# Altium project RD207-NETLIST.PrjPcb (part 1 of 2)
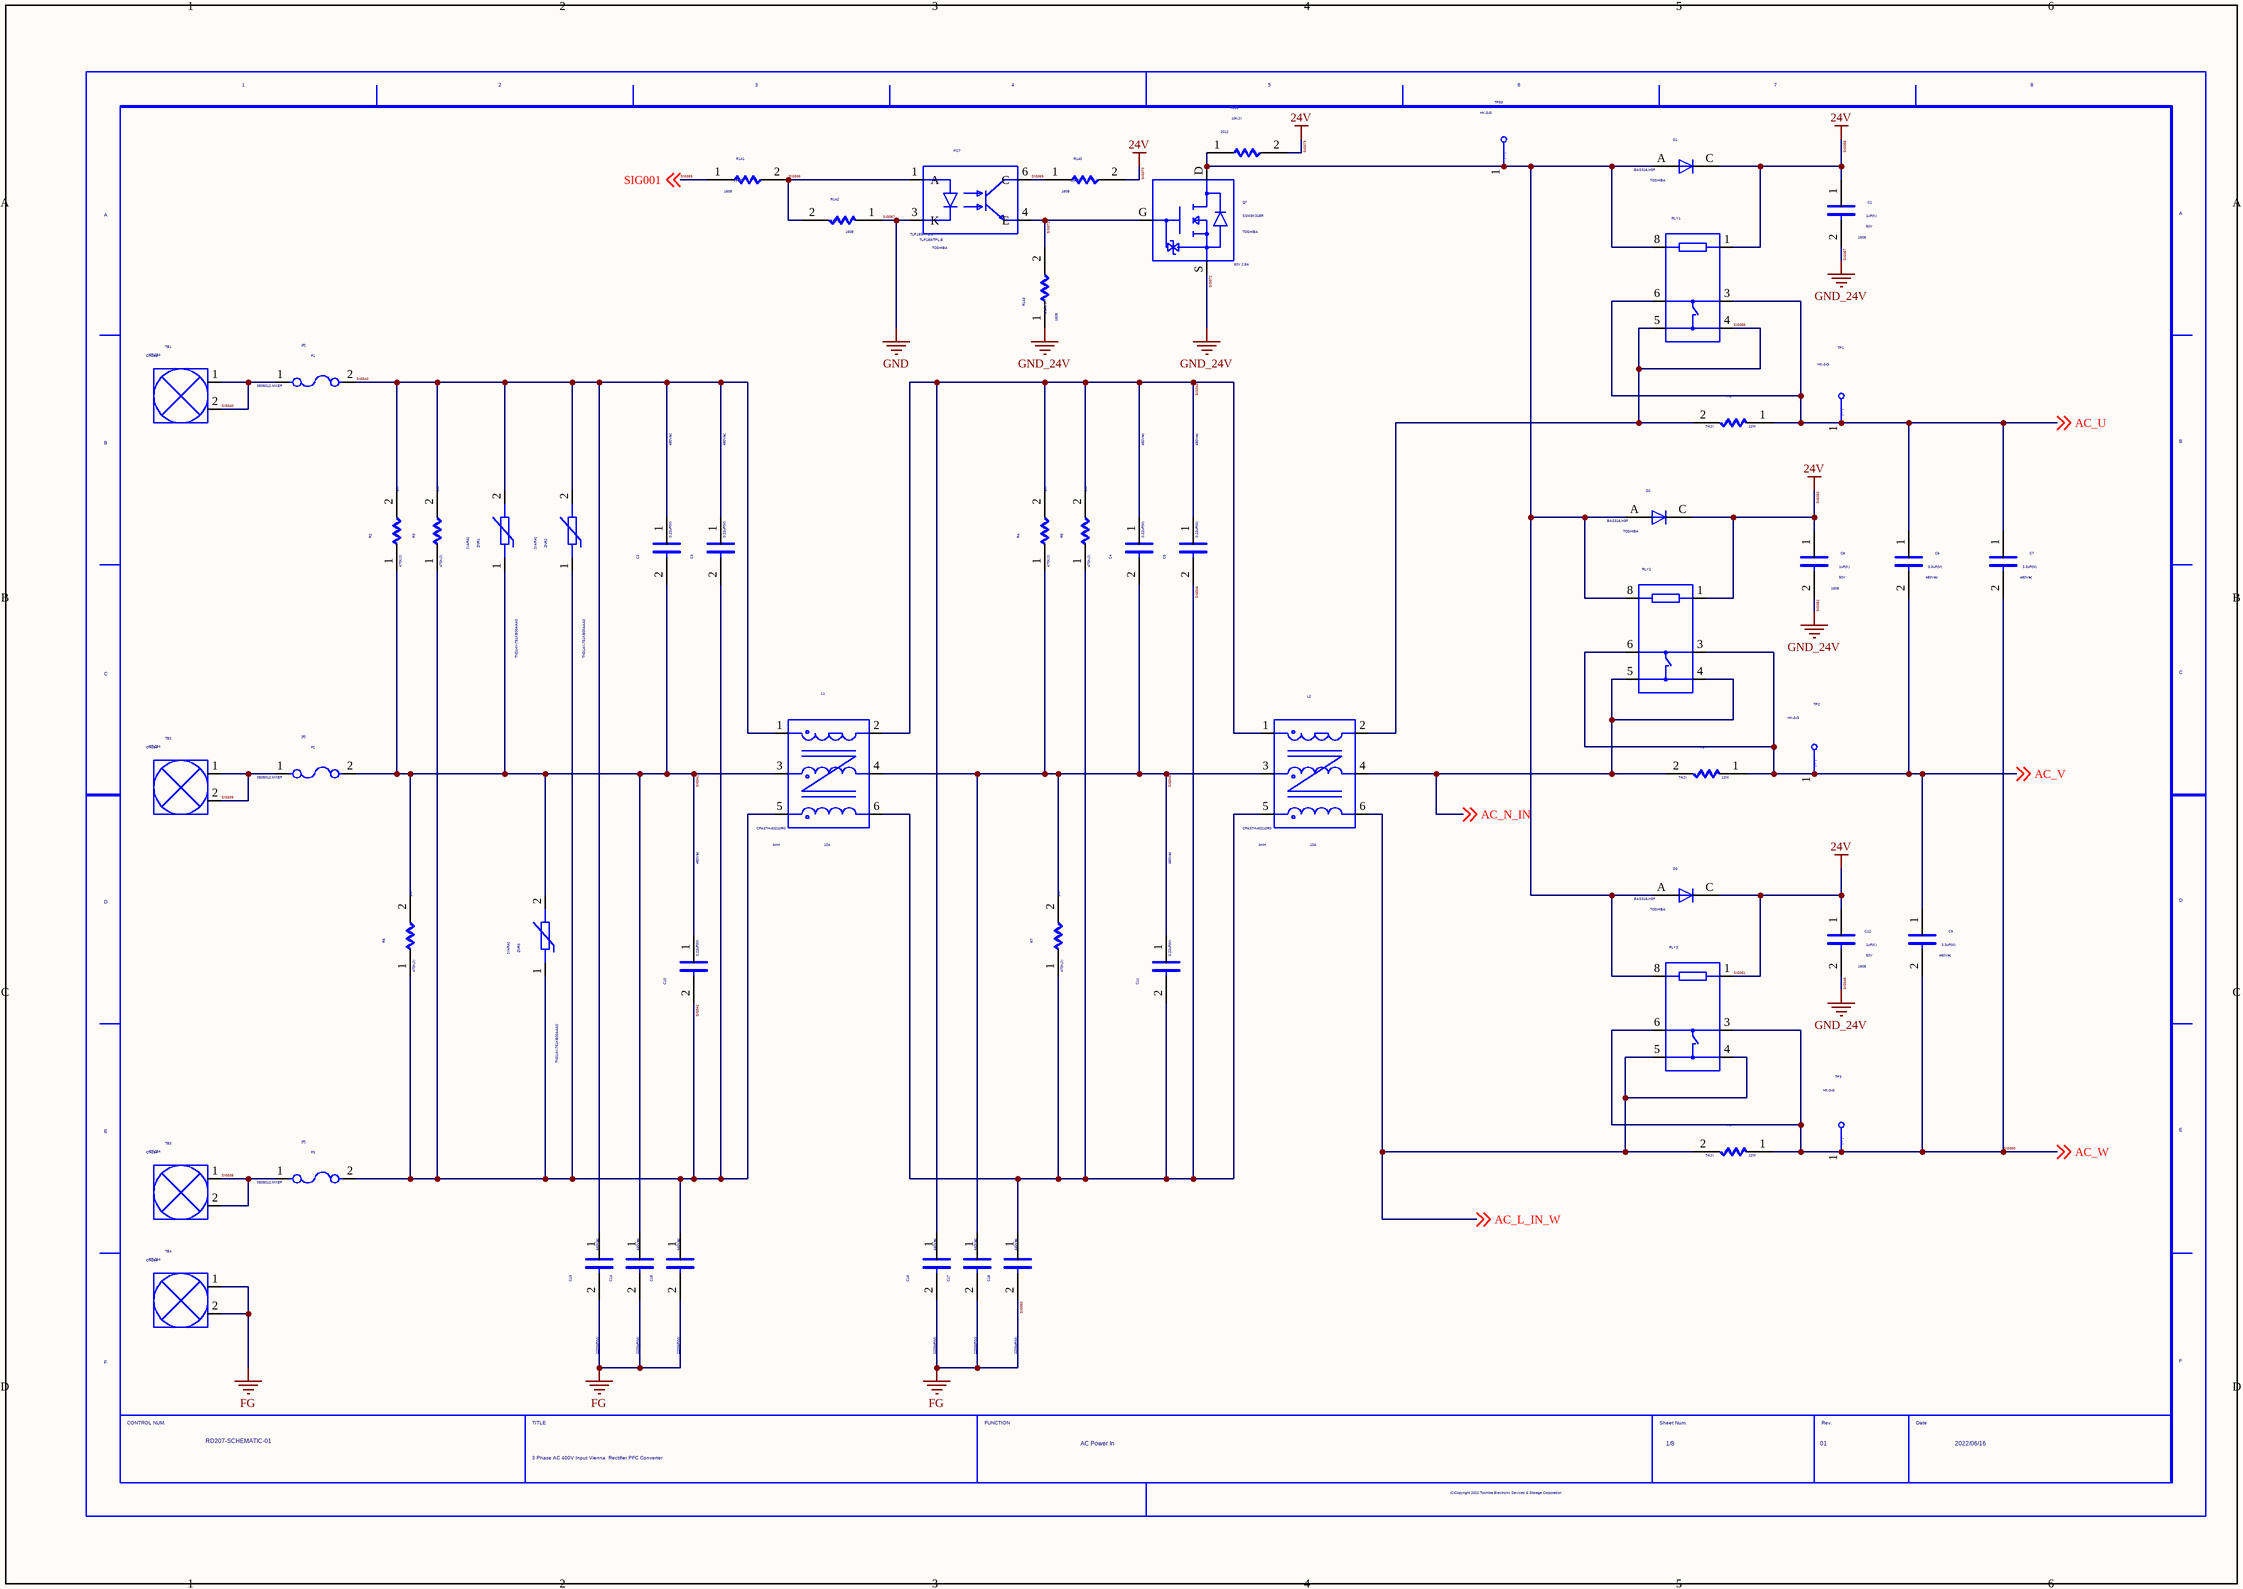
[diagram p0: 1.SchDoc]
8 sheets, 465 parts. Net scope: global (net labels, ports and power ports of the same name join across sheets).
Sheets:
  1.SchDoc
  2.SchDoc
  3.SchDoc
  4.SchDoc
  5.SchDoc
  6.SchDoc
  7.SchDoc
  8.SchDoc

## Sheet 1.SchDoc
size 420 x 297 mm

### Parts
(Parts that share a designator on the sheet are numbered #1, #2 ... from top to bottom, then left to right.)
C1  SIZECODESMD: 1608  VAL2: 50V  VAL1: 1uF(K)  (hidden comment: C)
C2  VAL2: 480Vac  VAL1: 0.22uF(M)  (hidden comment: C)
C3  VAL2: 480Vac  VAL1: 0.22uF(M)  (hidden comment: C)
C4  VAL2: 480Vac  VAL1: 0.22uF(M)  (hidden comment: C)
C5  VAL2: 480Vac  VAL1: 0.22uF(M)  (hidden comment: C)
C6  VAL2: 480Vac  VAL1: 3.3uF(M)  (hidden comment: C)
C7  VAL2: 480Vac  VAL1: 3.3uF(M)  (hidden comment: C)
C8  SIZECODESMD: 1608  VAL2: 50V  VAL1: 1uF(K)  (hidden comment: C)
C9  VAL2: 480Vac  VAL1: 3.3uF(M)  (hidden comment: C)
C10  VAL2: 480Vac  VAL1: 0.22uF(M)  (hidden comment: C)
C11  VAL2: 480Vac  VAL1: 0.22uF(M)  (hidden comment: C)
C12  SIZECODESMD: 1608  VAL2: 50V  VAL1: 1uF(K)  (hidden comment: C)
C13  VAL2: 440Vac  VAL1: 2200pF(M)  (hidden comment: C)
C14  VAL2: 440Vac  VAL1: 2200pF(M)  (hidden comment: C)
C15  VAL2: 440Vac  VAL1: 2200pF(M)  (hidden comment: C)
C16  VAL2: 440Vac  VAL1: 2200pF(M)  (hidden comment: C)
C17  VAL2: 440Vac  VAL1: 2200pF(M)  (hidden comment: C)
C18  VAL2: 440Vac  VAL1: 2200pF(M)  (hidden comment: C)
D1  USERCOMPTEXT3: TOSHIBA  VAL3: BAS316,H3F  (hidden comment: D)
D2  USERCOMPTEXT3: TOSHIBA  VAL3: BAS316,H3F  (hidden comment: D)
D3  USERCOMPTEXT3: TOSHIBA  VAL3: BAS316,H3F  (hidden comment: D)
F1  VAL3: 0505012.MXEP  (hidden comment: F)
F2  VAL3: 0505012.MXEP  (hidden comment: F)
F3  VAL3: 0505012.MXEP  (hidden comment: F)
L1  VAL2: 10A  VAL1: 4mH  (hidden comment: CFA37H-40210R0)
L2  VAL2: 10A  VAL1: 4mH  (hidden comment: CFA37H-40210R0)
PC7  TLP183(TPL,E  USERCOMPTEXT3: TOSHIBA
Q7  NOTE: 60V 2.5A  USERCOMPTEXT3: TOSHIBA  (hidden comment: SSM3K318R)
R1  VAL2: 12W  VAL1: 74(J)  (hidden comment: R)
R2  VAL2: 1W  VAL1: 470k(J)  (hidden comment: R)
R3  VAL2: 1W  VAL1: 470k(J)  (hidden comment: R)
R4  VAL2: 1W  VAL1: 470k(J)  (hidden comment: R)
R5  VAL2: 1W  VAL1: 470k(J)  (hidden comment: R)
R6  VAL2: 12W  VAL1: 74(J)  (hidden comment: R)
R7  VAL2: 1W  VAL1: 470k(J)  (hidden comment: R)
R8  VAL2: 1W  VAL1: 470k(J)  (hidden comment: R)
R9  VAL2: 12W  VAL1: 74(J)  (hidden comment: R)
R139  SIZECODESMD: 2012  VAL1: 10k(J)  (hidden comment: R)
R140  SIZECODESMD: 1608  VAL1: 10k(F)  (hidden comment: R)
R141  SIZECODESMD: 1608  VAL1: 390(F)  (hidden comment: R)
R142  SIZECODESMD: 1608  VAL1: 1k(F)  (hidden comment: R)
R143  SIZECODESMD: 1608  VAL1: 3.9k(F)  (hidden comment: R)
RLY1  G2RL-1A4-E-CF DC24  (value not drawn)
RLY2  G2RL-1A4-E-CF DC24  (value not drawn)
RLY3  G2RL-1A4-E-CF DC24  (value not drawn)
TB1  OT-264
TB2  OT-264
TB3  OT-264
TB4  OT-264
TP1  VAL3: HK-3-G  (hidden comment: TP)
TP2  VAL3: HK-3-G  (hidden comment: TP)
TP3  VAL3: HK-3-G  (hidden comment: TP)
TP50  VAL3: HK-3-G  (hidden comment: TP)
U?#1  DATE: 2022/06/16  TITLE: 3 Phase AC 400V Input Vienna / Rectifier PFC Converter  REVISION: 01  SHEETNUMBER: 1/8  FUNCTION: AC Power In  DRAWINGNUMBER: RD207-SCHEMATIC-01  (hidden comment: WAKU_DEF100)
ZNR1  VAL3: TND14V-751KB00AAA0  (hidden comment: VARA)
ZNR2  VAL3: TND14V-751KB00AAA0  (hidden comment: VARA)
ZNR3  VAL3: TND14V-751KB00AAA0  (hidden comment: VARA)

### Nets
GND: PC7.3(K) R142.1  [also labelled SIG367]  [project net SIG105]
SIG348: C1.2 C8.2 C12.2 Q7.S R143.1  [also labelled GND_24V, SIG352, SIG357, SIG372]
SIG350: C13.2 C14.2 C15.2 C16.2 C17.2 C18.2 TB4.1 TB4.2  [also labelled FG]
SIG351: C1.1 C8.1 C12.1 D1.C D2.C D3.C R139.2 R140.2 RLY1.1 RLY2.1 RLY3.1  [also labelled 24V, SIG353, SIG358, SIG370, SIG373]
/MainRLY_24V: D1.A D2.A D3.A Q7.D R139.1 RLY1.8 RLY2.8 RLY3.8 TP50.1
AC_L_IN_W: L2.6 R9.2 RLY3.4 RLY3.5 ; off-sheet AC_L_IN_W
AC_N_IN: L2.4 R6.2 RLY2.4 RLY2.5 ; off-sheet AC_N_IN
AC_U: C6.1 C7.1 R1.1 RLY1.3 RLY1.6 TP1.1 ; off-sheet AC_U
AC_V: C6.2 C9.1 R6.1 RLY2.3 RLY2.6 TP2.1 ; off-sheet AC_V
SIG338: F3.1 TB3.1 TB3.2
SIG339: F2.1 TB2.1 TB2.2
SIG340: F1.1 TB1.1 TB1.2
SIG341: C2.2 C10.1 C14.1 F2.2 L1.3 R2.1 R8.2 ZNR1.1 ZNR3.2
SIG342: C3.2 C10.2 C15.1 F3.2 L1.5 R3.1 R8.1 ZNR2.1 ZNR3.1
SIG343: C2.1 C3.1 C13.1 F1.2 L1.1 R2.2 R3.2 ZNR1.2 ZNR2.2
SIG344: C4.1 C5.1 C16.1 L1.2 L2.1 R4.2 R5.2
SIG345: C4.2 C11.1 C17.1 L1.4 L2.3 R4.1 R7.2
SIG346: C5.2 C11.2 C18.1 L1.6 L2.5 R5.1 R7.1
SIG356: L2.2 R1.2 RLY1.4 RLY1.5
SIG360: C7.2 C9.2 R9.1 RLY3.3 RLY3.6 TP3.1 ; off-sheet AC_W  [also labelled AC_W]
SIG365: R141.1 ; off-sheet SIG001  [also labelled SIG001]
SIG366: PC7.1(A) R141.2 R142.2
SIG369: PC7.6(C) R140.1
SIG371: PC7.4(E) Q7.G R143.2

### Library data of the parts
C1 C8 C12 = C: OriginalSymbolOrigin: (2540,7620); COMP: -C-UMK107AB7105KA-T
C2-C5 C10 C11 = C: OriginalSymbolOrigin: (2540,7620); COMP: -C-F339X142248MIP2T0
C6 C7 C9 = C: OriginalSymbolOrigin: (2540,7620); COMP: -C-F340X153348MPP2T0
C13-C18 = C: OriginalSymbolOrigin: (2540,7620); COMP: -C-CD45-E2GA222M-VKA
D1-D3 = D: SAVEAREA0: -225,-91,12804,7836; SAVECOUNT: 3; TIME: 14:49:55; UPDATEUSER: 19870035; UPDATETIME: 14:20:16; OriginalSymbolOrigin: (5080,5080); COMP: -D-BAS316_H3F_AC
F1-F3 = F: OriginalSymbolOrigin: (2540,5080); COMP: F-0505012.MXEP
L1 L2 = CFA37H_40210R0: 3phase Common Mode Choke; COMP: L-CFA37H-40210R0; MAKER: Tamura; NOTE: 3phase, 4mH@100kHz, 10A; TIME: 11:39:42; UPDATEUSER: t5459927; UPDATETIME: 15:32:41; SAVECOUNT: 2; SAVEAREA0: -28588,-28970,43380,3822; OriginalSymbolOrigin: (0,0)
PC7 = TLP183: Photocoupler; COMP: -PC-TLP183_TPL_E; TIME: 11:39:41; UPDATEUSER: t5459927; UPDATETIME: 14:44:44; SAVECOUNT: 2; SAVEAREA0: -18362,-25993,35930,13752; OriginalSymbolOrigin: (0,0)
Q7 = SSM3K318R: MOSFET; COMP: -Q-SSM3K318R; TIME: 11:39:41; UPDATEUSER: t5459927; SAVECOUNT: 1; SAVEAREA0: -8920,-18190,20944,3672; OriginalSymbolOrigin: (0,0); INSTANCENAME: INS17447591
R1 R6 R9 = R: OriginalSymbolOrigin: (5080,5080); COMP: R-MNG12E740JC
R2-R5 R7 R8 = R: OriginalSymbolOrigin: (5080,5080); COMP: -R-RCR60C474J
R139 = R: OriginalSymbolOrigin: (5080,5080); VAL2: 250mW; COMP: -R-RK73B2ATTD103J
R140 = R: OriginalSymbolOrigin: (5080,5080); VAL2: 100mW; COMP: -R-ERJ3EKF1002V
R141 = R: OriginalSymbolOrigin: (5080,5080); VAL2: 100mW; COMP: -R-ERJ3EKF3900V
R142 = R: OriginalSymbolOrigin: (5080,5080); VAL2: 125mW; COMP: -R-RK73H1JTTD1001F
R143 = R: OriginalSymbolOrigin: (5080,5080); VAL2: 100mW; COMP: -R-ERJ3EKF3901V
RLY1-RLY3 = G2RL_1A4_E_CF_DC24: Power Relay; MANUFACTURER: OMRON; COMP: -RLY-G2RL-1A4-E-CF_DC24; NOTE: 16A AC250V; TIME: 11:39:42; UPDATEUSER: t5459927; UPDATETIME: 16:09:17; SAVECOUNT: 4; SAVEAREA0: -30398,-23390,50563,13500; OriginalSymbolOrigin: (5080,7620)
TB1-TB4 = OT_264: Terminal, 50A, M4; MANUFACTURER: Osada; COMP: -TB-OT-264; TIME: 11:39:39; UPDATEUSER: t5459927; SAVECOUNT: 1; SAVEAREA0: -3825,-10384,11105,546; OriginalSymbolOrigin: (0,0); REFERENCE TEMPLATE: TB; INSTANCENAME: INS1928
TP1-TP3 TP50 = TP: TIME: 16:12:21; UPDATEUSER: fukuda-y; UPDATETIME: 16:18:11; SAVECOUNT: 2; SAVEAREA0: -242,-92,12810,7836; OriginalSymbolOrigin: (0,7620); COMP: -TP-HK-3-G
U?#1 = WAKU_DEF100: PLOTTIME: HH:MM; SAVEAREA0: 22200,72372,612276,319236; TIME: 14:30:25; UPDATEUSER: t5459927; UPDATETIME: 09:21:32; SAVECOUNT: 7; OriginalSymbolOrigin: (10160,284480)
ZNR1-ZNR3 = VARA: SAVEAREA0: -9950,-8554,25168,13619; SAVECOUNT: 12; TIME: 09:56:50; UPDATEUSER: tomizawa-y; OriginalSymbolOrigin: (2540,5080); COMP: -ZNR-TND14V-751KB00AAA0

## Sheet 2.SchDoc
size 420 x 297 mm
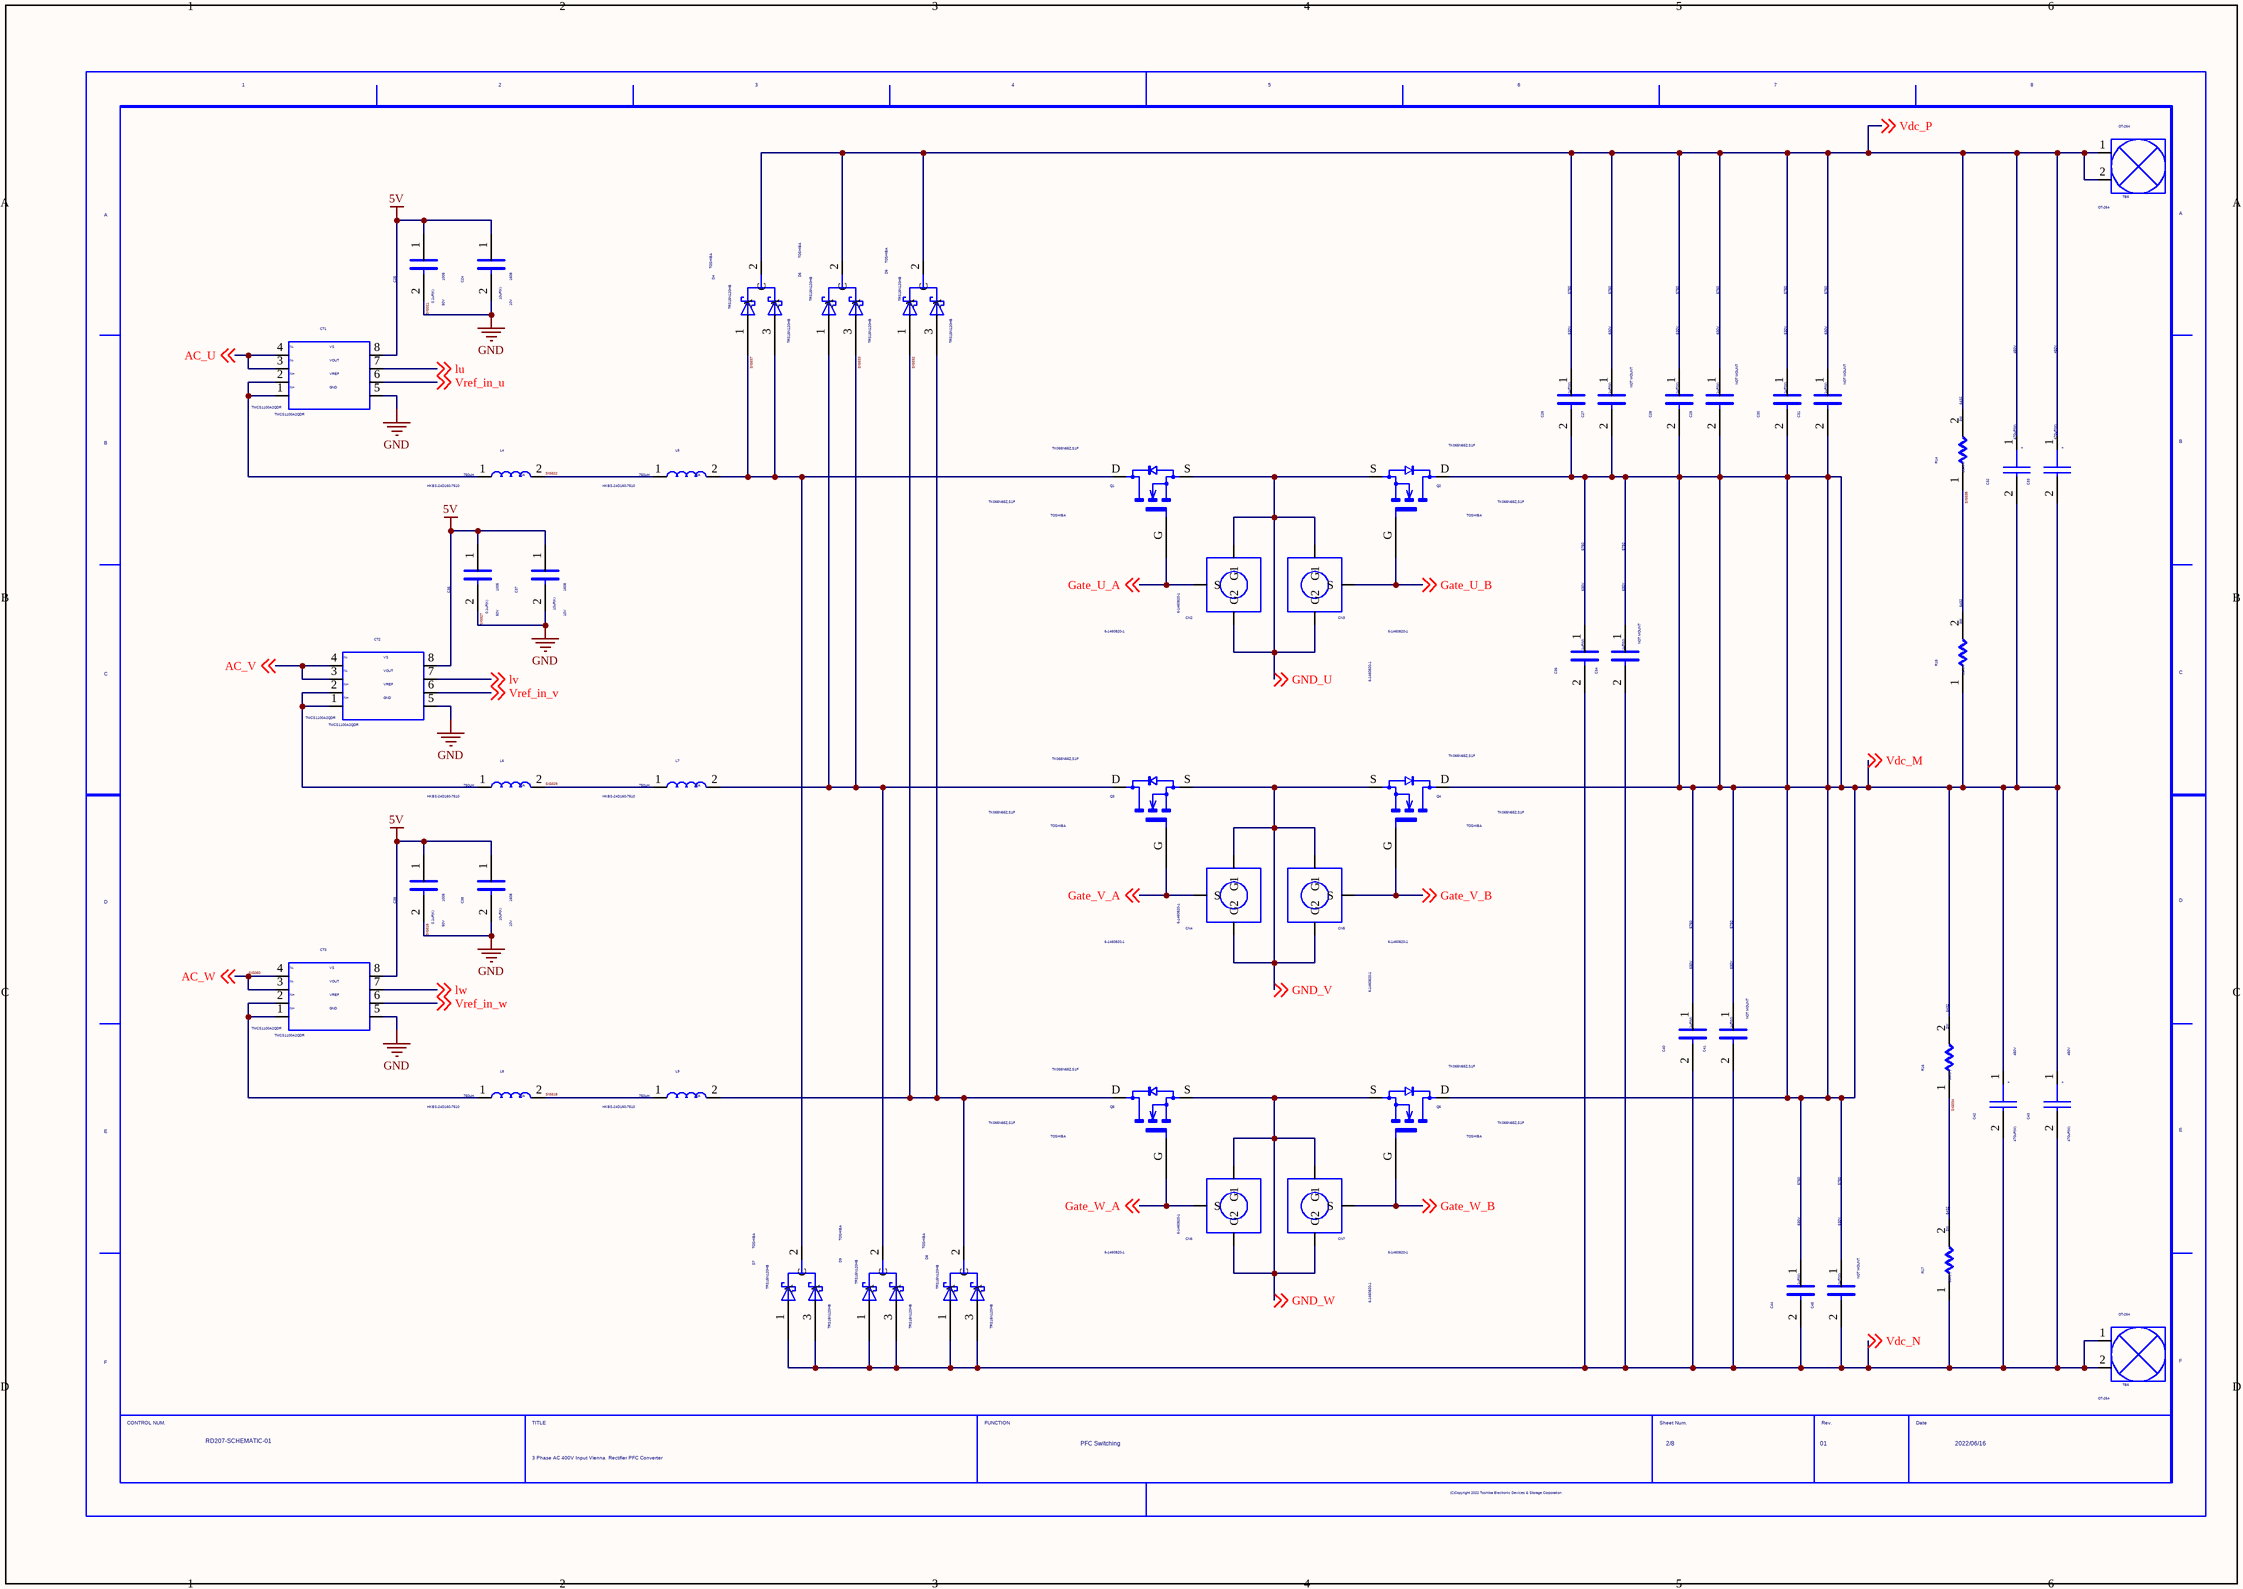
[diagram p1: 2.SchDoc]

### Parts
(Parts that share a designator on the sheet are numbered #1, #2 ... from top to bottom, then left to right.)
C24  SIZECODESMD: 1608  VAL2: 10V  VAL1: 10uF(K)  (hidden comment: C)
C25  SIZECODESMD: 1005  VAL2: 50V  VAL1: 0.1uF(K)  (hidden comment: C)
C26  SIZECODESMD: 5750  VAL2: 630V  VAL1: 1uF(M)  (hidden comment: C)
C27  NOTMOUNT: NOT MOUNT  SIZECODESMD: 5750  VAL2: 630V  VAL1: 1uF(M)  (hidden comment: C)
C28  SIZECODESMD: 5750  VAL2: 630V  VAL1: 1uF(M)  (hidden comment: C)
C29  NOTMOUNT: NOT MOUNT  SIZECODESMD: 5750  VAL2: 630V  VAL1: 1uF(M)  (hidden comment: C)
C30  SIZECODESMD: 5750  VAL2: 630V  VAL1: 1uF(M)  (hidden comment: C)
C31  NOTMOUNT: NOT MOUNT  SIZECODESMD: 5750  VAL2: 630V  VAL1: 1uF(M)  (hidden comment: C)
C32  VAL2: 450V  VAL1: 470uF(M)  (hidden comment: CP)
C33  VAL2: 450V  VAL1: 470uF(M)  (hidden comment: CP)
C34  NOTMOUNT: NOT MOUNT  SIZECODESMD: 5750  VAL2: 630V  VAL1: 1uF(M)  (hidden comment: C)
C35  SIZECODESMD: 1005  VAL2: 50V  VAL1: 0.1uF(K)  (hidden comment: C)
C36  SIZECODESMD: 5750  VAL2: 630V  VAL1: 1uF(M)  (hidden comment: C)
C37  SIZECODESMD: 1608  VAL2: 10V  VAL1: 10uF(K)  (hidden comment: C)
C38  SIZECODESMD: 1608  VAL2: 10V  VAL1: 10uF(K)  (hidden comment: C)
C39  SIZECODESMD: 1005  VAL2: 50V  VAL1: 0.1uF(K)  (hidden comment: C)
C40  SIZECODESMD: 5750  VAL2: 630V  VAL1: 1uF(M)  (hidden comment: C)
C41  NOTMOUNT: NOT MOUNT  SIZECODESMD: 5750  VAL2: 630V  VAL1: 1uF(M)  (hidden comment: C)
C42  VAL2: 450V  VAL1: 470uF(M)  (hidden comment: CP)
C43  VAL2: 450V  VAL1: 470uF(M)  (hidden comment: CP)
C44  SIZECODESMD: 5750  VAL2: 630V  VAL1: 1uF(M)  (hidden comment: C)
C45  NOTMOUNT: NOT MOUNT  SIZECODESMD: 5750  VAL2: 630V  VAL1: 1uF(M)  (hidden comment: C)
CN2  6-1460820-1
CN3  6-1460820-1
CN4  6-1460820-1
CN5  6-1460820-1
CN6  6-1460820-1
CN7  6-1460820-1
CT1  TMCS1100A2QDR
CT2  TMCS1100A2QDR
CT3  TMCS1100A2QDR
D4  TRS15N120HB  USERCOMPTEXT3: TOSHIBA
D5  TRS15N120HB  USERCOMPTEXT3: TOSHIBA
D6  TRS15N120HB  USERCOMPTEXT3: TOSHIBA
D7  TRS15N120HB  USERCOMPTEXT3: TOSHIBA
D8  TRS15N120HB  USERCOMPTEXT3: TOSHIBA
D9  TRS15N120HB  USERCOMPTEXT3: TOSHIBA
L4  VAL3: HKBS-24D160-7510  VAL2: 10A  VAL1: 750uH  (hidden comment: L)
L5  VAL3: HKBS-24D160-7510  VAL2: 10A  VAL1: 750uH  (hidden comment: L)
L6  VAL3: HKBS-24D160-7510  VAL2: 10A  VAL1: 750uH  (hidden comment: L)
L7  VAL3: HKBS-24D160-7510  VAL2: 10A  VAL1: 750uH  (hidden comment: L)
L8  VAL3: HKBS-24D160-7510  VAL2: 10A  VAL1: 750uH  (hidden comment: L)
L9  VAL3: HKBS-24D160-7510  VAL2: 10A  VAL1: 750uH  (hidden comment: L)
Q1  TK065N65Z,S1F  USERCOMPTEXT3: TOSHIBA
Q2  TK065N65Z,S1F  USERCOMPTEXT3: TOSHIBA
Q3  TK065N65Z,S1F  USERCOMPTEXT3: TOSHIBA
Q4  TK065N65Z,S1F  USERCOMPTEXT3: TOSHIBA
Q5  TK065N65Z,S1F  USERCOMPTEXT3: TOSHIBA
Q6  TK065N65Z,S1F  USERCOMPTEXT3: TOSHIBA
R14  SIZECODESMD: 6432  VAL2: 3W  VAL1: 39k(F)  (hidden comment: R)
R15  SIZECODESMD: 6432  VAL2: 3W  VAL1: 39k(F)  (hidden comment: R)
R16  SIZECODESMD: 6432  VAL2: 3W  VAL1: 39k(F)  (hidden comment: R)
R17  SIZECODESMD: 6432  VAL2: 3W  VAL1: 39k(F)  (hidden comment: R)
TB5  OT-264
TB6  OT-264
U?#2  DATE: 2022/06/16  TITLE: 3 Phase AC 400V Input Vienna / Rectifier PFC Converter  DRAWINGNUMBER: RD207-SCHEMATIC-01  REVISION: 01  SHEETNUMBER: 2/8  FUNCTION: PFC Switching  (hidden comment: WAKU_DEF100)

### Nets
5V: C24.1 C25.1 C35.1 C37.1 C38.1 C39.1 CT1.8 CT2.8 CT3.8  [also labelled SIG314, SIG328]  [project net SIG104]
GND: C24.2 C25.2 C35.2 C37.2 C38.2 C39.2 CT1.5 CT2.5 CT3.5  [also labelled SIG315, SIG321, SIG327]  [project net SIG105]
GND_U: CN2.G1 CN2.G2 CN3.G1 CN3.G2 Q1.S Q2.S ; off-sheet GND_U
GND_V: CN4.G1 CN4.G2 CN5.G1 CN5.G2 Q3.S Q4.S ; off-sheet GND_V
GND_W: CN6.G1 CN6.G2 CN7.G1 CN7.G2 Q5.S Q6.S ; off-sheet GND_W
AC_U: CT1.3 CT1.4 ; off-sheet AC_U
AC_V: CT2.3 CT2.4 ; off-sheet AC_V
Gate_U_A: CN2.S Q1.G ; off-sheet Gate_U_A
Gate_U_B: CN3.S Q2.G ; off-sheet Gate_U_B
Gate_V_A: CN4.S Q3.G ; off-sheet Gate_V_A
Gate_V_B: CN5.S Q4.G ; off-sheet Gate_V_B
Gate_W_A: CN6.S Q5.G ; off-sheet Gate_W_A
Gate_W_B: CN7.S Q6.G ; off-sheet Gate_W_B
lu: CT1.7 ; off-sheet lu
lv: CT2.7 ; off-sheet lv
lw: CT3.7 ; off-sheet lw
SIG317: CT3.1 CT3.2 L8.1
SIG318: L8.2 L9.1
SIG322: L4.2 L5.1
SIG325: CT1.1 CT1.2 L4.1
SIG329: L6.2 L7.1
SIG330: CT2.1 CT2.2 L6.1
SIG332: D6.1(A) D6.3(A) D8.2(C) L9.2 Q5.D
SIG333: D5.1(A) D5.3(A) D9.2(C) L7.2 Q3.D
SIG334: R16.1 R17.2
SIG335: R14.1 R15.2
SIG337: D4.1(A) D4.3(A) D7.2(C) L5.2 Q1.D
SIG360: CT3.3 CT3.4 ; off-sheet AC_W  [also labelled AC_W]
Vdc_M: C26.2 C27.2 C28.2 C29.2 C30.2 C31.2 C32.2 C33.2 C34.1 C36.1 C40.1 C41.1 C42.1 C43.1 C44.1 C45.1 Q2.D Q4.D Q6.D R15.1 R16.2 ; off-sheet Vdc_M
Vdc_N: C34.2 C36.2 C40.2 C41.2 C42.2 C43.2 C44.2 C45.2 D7.1(A) D7.3(A) D8.1(A) D8.3(A) D9.1(A) D9.3(A) R17.1 TB6.1 TB6.2 ; off-sheet Vdc_N
Vdc_P: C26.1 C27.1 C28.1 C29.1 C30.1 C31.1 C32.1 C33.1 D4.2(C) D5.2(C) D6.2(C) R14.2 TB5.1 TB5.2 ; off-sheet Vdc_P
Vref_in_u: CT1.6 ; off-sheet Vref_in_u
Vref_in_v: CT2.6 ; off-sheet Vref_in_v
Vref_in_w: CT3.6 ; off-sheet Vref_in_w

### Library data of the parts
C24 C37 C38 = C: OriginalSymbolOrigin: (2540,7620); COMP: -C-GRM188D71A106KA73D
C25 C35 C39 = C: OriginalSymbolOrigin: (2540,7620); COMP: -C-UMK105BJ104KV-F
C26 C28 C30 C36 C40 C44 = C: OriginalSymbolOrigin: (2540,7620); COMP: -C-CAA572X7T2J105M640LH
C27 C29 C31 C34 C41 C45 = C: OriginalSymbolOrigin: (2540,7620); COMP: -C-NC_CAA572X7T2J105M640LH
C32 C33 C42 C43 = CP: SAVEAREA0: -1450,-153,20294,13055; SAVECOUNT: 52; TIME: 15:02:55; UPDATEUSER: fukuda-y; UPDATETIME: 16:13:42; OriginalSymbolOrigin: (2540,10160); COMP: -C-450MXK470MEFCSN25X55
CN2-CN7 = 6_1460820_1: MMCX Connector, 170V; MANUFACTURER: TE Connectivity; COMP: CN-6-1460820-1_Micro_SP-NoTH; TIME: 11:39:41; UPDATEUSER: t5459927; UPDATETIME: 13:55:13; SAVECOUNT: 2; SAVEAREA0: -9060,-19760,18940,737; OriginalSymbolOrigin: (0,0)
CT1-CT3 = TMCS1100A2QDR: COMP: -CT-TMCS1100A2QDR; TIME: 11:39:42; UPDATEUSER: t5459927; UPDATETIME: 14:02:58; SAVECOUNT: 5; SAVEAREA0: -9737,-18768,24721,6457; OriginalSymbolOrigin: (0,0)
D4 = TRS15N120HB: SiC Schottky Barrier Diode Array; COMP: D-TRS15N120HB; NOTE: 1200V; TIME: 11:39:42; UPDATEUSER: t5459927; SAVECOUNT: 1; OriginalSymbolOrigin: (0,0); INSTANCENAME: INS17355299
D5 = TRS15N120HB: SiC Schottky Barrier Diode Array; COMP: D-TRS15N120HB; NOTE: 1200V; TIME: 11:39:42; UPDATEUSER: t5459927; SAVECOUNT: 1; OriginalSymbolOrigin: (0,0); INSTANCENAME: INS17355445
D6 = TRS15N120HB: SiC Schottky Barrier Diode Array; COMP: D-TRS15N120HB; NOTE: 1200V; TIME: 11:39:42; UPDATEUSER: t5459927; SAVECOUNT: 1; OriginalSymbolOrigin: (0,0); INSTANCENAME: INS17355424
D7 = TRS15N120HB: SiC Schottky Barrier Diode Array; COMP: D-TRS15N120HB_SP; NOTE: 1200V; TIME: 11:39:42; UPDATEUSER: t5459927; SAVECOUNT: 1; OriginalSymbolOrigin: (0,0); INSTANCENAME: INS17355299
D8 = TRS15N120HB: SiC Schottky Barrier Diode Array; COMP: D-TRS15N120HB_SP; NOTE: 1200V; TIME: 11:39:42; UPDATEUSER: t5459927; SAVECOUNT: 1; OriginalSymbolOrigin: (0,0); INSTANCENAME: INS17355424
D9 = TRS15N120HB: SiC Schottky Barrier Diode Array; COMP: D-TRS15N120HB_SP; NOTE: 1200V; TIME: 11:39:42; UPDATEUSER: t5459927; SAVECOUNT: 1; OriginalSymbolOrigin: (0,0); INSTANCENAME: INS17355445
L4-L9 = L: OriginalSymbolOrigin: (2540,5080); COMP: L-HKBS-24D160-7510
Q1-Q6 = TK065N65Z_S1F: Power MOS FET; COMP: Q-TK065N65Z_TATE; NOTE: 650V 30A; TIME: 11:39:42; UPDATEUSER: t5459927; UPDATETIME: 13:16:21; SAVECOUNT: 2; SAVEAREA0: -16850,-13021,18411,3375; OriginalSymbolOrigin: (0,0)
R14-R17 = R: OriginalSymbolOrigin: (5080,5080); COMP: -R-352239KFT
TB5 TB6 = OT_264: Terminal, 50A, M4; MANUFACTURER: Osada; COMP: -TB-OT-264; TIME: 11:39:39; UPDATEUSER: t5459927; UPDATETIME: 13:18:21; SAVECOUNT: 2; SAVEAREA0: -3825,-10384,11105,546; OriginalSymbolOrigin: (0,0)
U?#2 = WAKU_DEF100: as U?#1 on sheet 1

## Sheet 3.SchDoc
size 420 x 297 mm
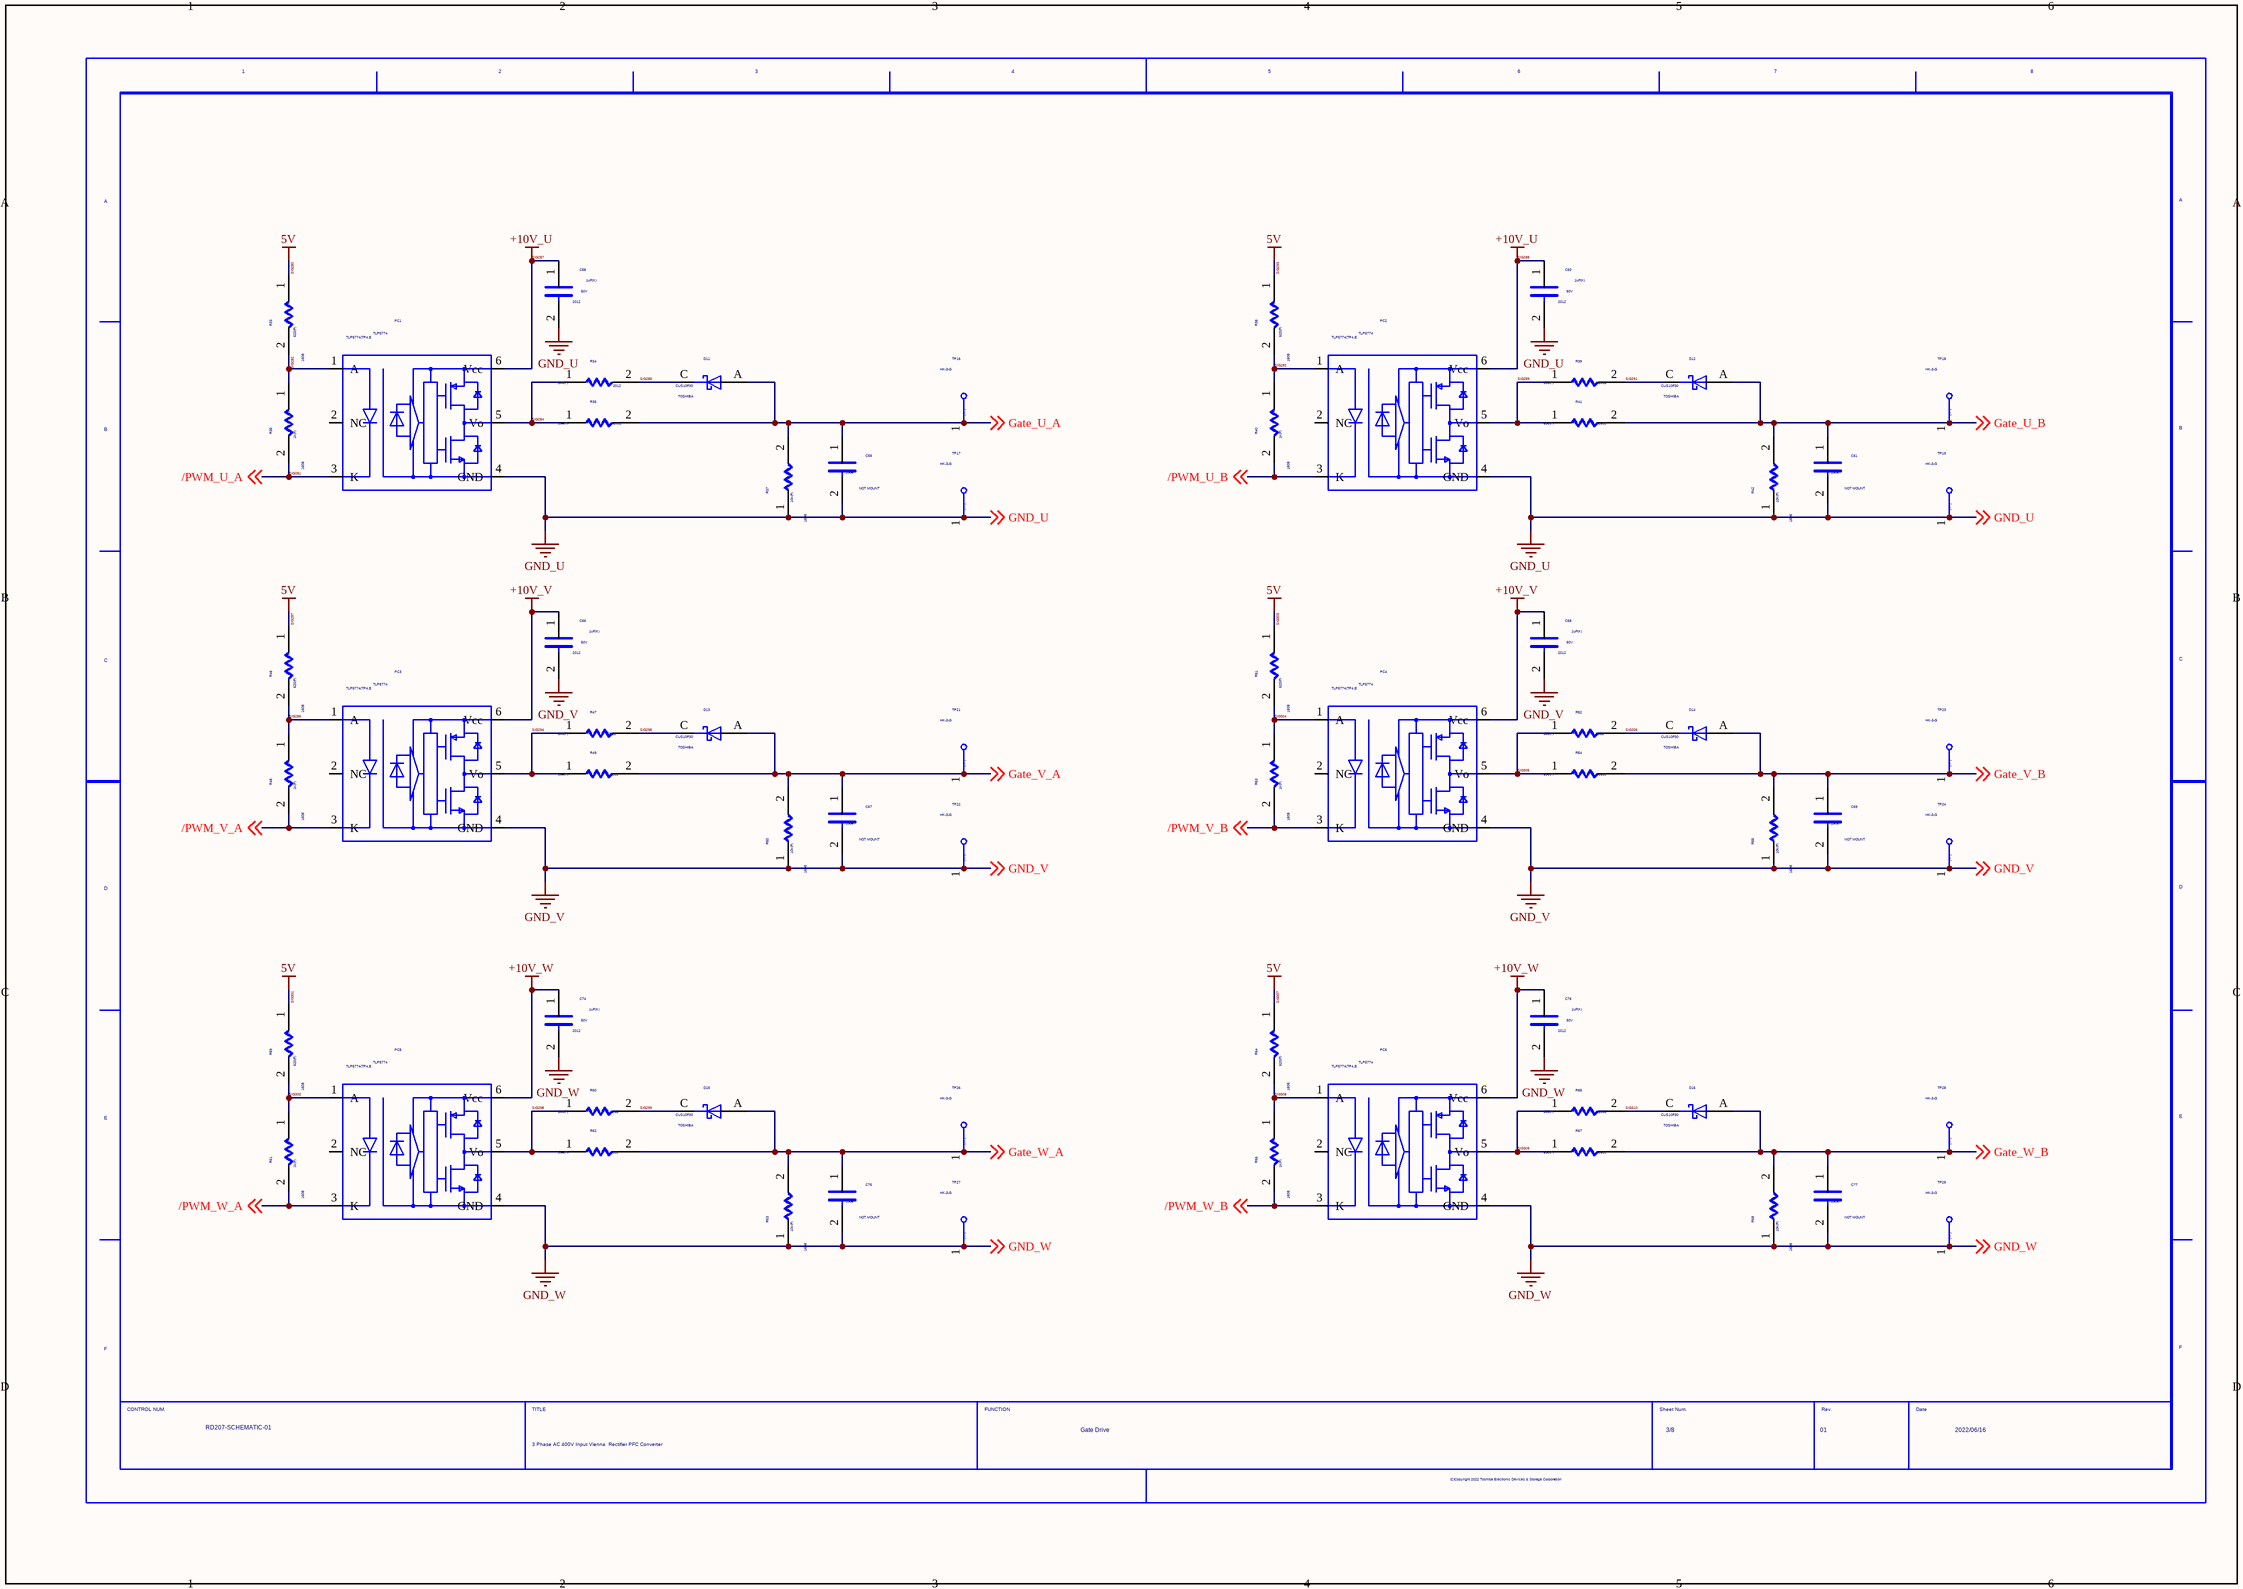
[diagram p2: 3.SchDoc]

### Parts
(Parts that share a designator on the sheet are numbered #1, #2 ... from top to bottom, then left to right.)
C58  SIZECODESMD: 2012  VAL2: 50V  VAL1: 1uF(K)  (hidden comment: C)
C59  SIZECODESMD: 1608  NOTMOUNT: NOT MOUNT  (hidden comment: C)
C60  SIZECODESMD: 2012  VAL2: 50V  VAL1: 1uF(K)  (hidden comment: C)
C61  SIZECODESMD: 1608  NOTMOUNT: NOT MOUNT  (hidden comment: C)
C66  SIZECODESMD: 2012  VAL2: 50V  VAL1: 1uF(K)  (hidden comment: C)
C67  SIZECODESMD: 1608  NOTMOUNT: NOT MOUNT  (hidden comment: C)
C68  SIZECODESMD: 2012  VAL2: 50V  VAL1: 1uF(K)  (hidden comment: C)
C69  SIZECODESMD: 1608  NOTMOUNT: NOT MOUNT  (hidden comment: C)
C74  SIZECODESMD: 2012  VAL2: 50V  VAL1: 1uF(K)  (hidden comment: C)
C75  SIZECODESMD: 1608  NOTMOUNT: NOT MOUNT  (hidden comment: C)
C76  SIZECODESMD: 2012  VAL2: 50V  VAL1: 1uF(K)  (hidden comment: C)
C77  SIZECODESMD: 1608  NOTMOUNT: NOT MOUNT  (hidden comment: C)
D11  USERCOMPTEXT3: TOSHIBA  VAL3: CUS10F30  (hidden comment: SBD)
D12  USERCOMPTEXT3: TOSHIBA  VAL3: CUS10F30  (hidden comment: SBD)
D13  USERCOMPTEXT3: TOSHIBA  VAL3: CUS10F30  (hidden comment: SBD)
D14  USERCOMPTEXT3: TOSHIBA  VAL3: CUS10F30  (hidden comment: SBD)
D15  USERCOMPTEXT3: TOSHIBA  VAL3: CUS10F30  (hidden comment: SBD)
D16  USERCOMPTEXT3: TOSHIBA  VAL3: CUS10F30  (hidden comment: SBD)
PC1  TLP5774  VAL3: TLP5774(TP4,E
PC2  TLP5774  VAL3: TLP5774(TP4,E
PC3  TLP5774  VAL3: TLP5774(TP4,E
PC4  TLP5774  VAL3: TLP5774(TP4,E
PC5  TLP5774  VAL3: TLP5774(TP4,E
PC6  TLP5774  VAL3: TLP5774(TP4,E
R33  SIZECODESMD: 1608  VAL1: 620(F)  (hidden comment: R)
R34  SIZECODESMD: 2012  VAL1: 100(F)  (hidden comment: R)
R35  SIZECODESMD: 1608  VAL1: 1k(F)  (hidden comment: R)
R36  SIZECODESMD: 2012  VAL1: 100(F)  (hidden comment: R)
R37  SIZECODESMD: 1608  VAL1: 10k(F)  (hidden comment: R)
R38  SIZECODESMD: 1608  VAL1: 620(F)  (hidden comment: R)
R39  SIZECODESMD: 2012  VAL1: 100(F)  (hidden comment: R)
R40  SIZECODESMD: 1608  VAL1: 1k(F)  (hidden comment: R)
R41  SIZECODESMD: 2012  VAL1: 100(F)  (hidden comment: R)
R42  SIZECODESMD: 1608  VAL1: 10k(F)  (hidden comment: R)
R46  SIZECODESMD: 1608  VAL1: 620(F)  (hidden comment: R)
R47  SIZECODESMD: 2012  VAL1: 100(F)  (hidden comment: R)
R48  SIZECODESMD: 1608  VAL1: 1k(F)  (hidden comment: R)
R49  SIZECODESMD: 2012  VAL1: 100(F)  (hidden comment: R)
R50  SIZECODESMD: 1608  VAL1: 10k(F)  (hidden comment: R)
R51  SIZECODESMD: 1608  VAL1: 620(F)  (hidden comment: R)
R52  SIZECODESMD: 2012  VAL1: 100(F)  (hidden comment: R)
R53  SIZECODESMD: 1608  VAL1: 1k(F)  (hidden comment: R)
R54  SIZECODESMD: 2012  VAL1: 100(F)  (hidden comment: R)
R55  SIZECODESMD: 1608  VAL1: 10k(F)  (hidden comment: R)
R59  SIZECODESMD: 1608  VAL1: 620(F)  (hidden comment: R)
R60  SIZECODESMD: 2012  VAL1: 100(F)  (hidden comment: R)
R61  SIZECODESMD: 1608  VAL1: 1k(F)  (hidden comment: R)
R62  SIZECODESMD: 2012  VAL1: 100(F)  (hidden comment: R)
R63  SIZECODESMD: 1608  VAL1: 10k(F)  (hidden comment: R)
R64  SIZECODESMD: 1608  VAL1: 620(F)  (hidden comment: R)
R65  SIZECODESMD: 2012  VAL1: 100(F)  (hidden comment: R)
R66  SIZECODESMD: 1608  VAL1: 1k(F)  (hidden comment: R)
R67  SIZECODESMD: 2012  VAL1: 100(F)  (hidden comment: R)
R68  SIZECODESMD: 1608  VAL1: 10k(F)  (hidden comment: R)
TP16  VAL3: HK-3-G  (hidden comment: TP)
TP17  VAL3: HK-3-G  (hidden comment: TP)
TP18  VAL3: HK-3-G  (hidden comment: TP)
TP19  VAL3: HK-3-G  (hidden comment: TP)
TP21  VAL3: HK-3-G  (hidden comment: TP)
TP22  VAL3: HK-3-G  (hidden comment: TP)
TP23  VAL3: HK-3-G  (hidden comment: TP)
TP24  VAL3: HK-3-G  (hidden comment: TP)
TP26  VAL3: HK-3-G  (hidden comment: TP)
TP27  VAL3: HK-3-G  (hidden comment: TP)
TP28  VAL3: HK-3-G  (hidden comment: TP)
TP29  VAL3: HK-3-G  (hidden comment: TP)
U?#3  DATE: 2022/06/16  TITLE: 3 Phase AC 400V Input Vienna / Rectifier PFC Converter  REVISION: 01  SHEETNUMBER: 3/8  FUNCTION: Gate Drive  DRAWINGNUMBER: RD207-SCHEMATIC-01  (hidden comment: WAKU_DEF100)

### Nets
5V: R33.1 R38.1 R46.1 R51.1 R59.1 R64.1  [also labelled SIG280, SIG293, SIG297, SIG301, SIG303, SIG307]  [project net SIG104]
+10V_V: C66.1 C68.1 PC3.6(Vcc) PC4.6(Vcc)
+10V_W: C74.1 C76.1 PC5.6(Vcc) PC6.6(Vcc)
GND_U: C58.2 C59.2 C60.2 C61.2 PC1.4(GND) PC2.4(GND) R37.1 R42.1 TP17.1 TP19.1 ; off-sheet GND_U
GND_V: C66.2 C67.2 C68.2 C69.2 PC3.4(GND) PC4.4(GND) R50.1 R55.1 TP22.1 TP24.1 ; off-sheet GND_V
GND_W: C74.2 C75.2 C76.2 C77.2 PC5.4(GND) PC6.4(GND) R63.1 R68.1 TP27.1 TP29.1 ; off-sheet GND_W
SIG287: C58.1 C60.1 PC1.6(Vcc) PC2.6(Vcc)  [also labelled +10V_U, SIG288]
/PWM_U_B: PC2.3(K) R40.2 ; off-sheet /PWM_U_B
/PWM_V_A: PC3.3(K) R48.2 ; off-sheet /PWM_V_A
/PWM_V_B: PC4.3(K) R53.2 ; off-sheet /PWM_V_B
/PWM_W_A: PC5.3(K) R61.2 ; off-sheet /PWM_W_A
/PWM_W_B: PC6.3(K) R66.2 ; off-sheet /PWM_W_B
Gate_U_A: C59.1 D11.A R36.2 R37.2 TP16.1 ; off-sheet Gate_U_A
Gate_U_B: C61.1 D12.A R41.2 R42.2 TP18.1 ; off-sheet Gate_U_B
Gate_V_A: C67.1 D13.A R49.2 R50.2 TP21.1 ; off-sheet Gate_V_A
Gate_V_B: C69.1 D14.A R54.2 R55.2 TP23.1 ; off-sheet Gate_V_B
Gate_W_A: C75.1 D15.A R62.2 R63.2 TP26.1 ; off-sheet Gate_W_A
Gate_W_B: C77.1 D16.A R67.2 R68.2 TP28.1 ; off-sheet Gate_W_B
SIG281: PC1.3(K) R35.2 ; off-sheet /PWM_U_A  [also labelled /PWM_U_A]
SIG282: PC1.1(A) R33.2 R35.1
SIG284: PC1.5(Vo) R34.1 R36.1
SIG285: D11.C R34.2
SIG289: PC2.5(Vo) R39.1 R41.1
SIG291: D12.C R39.2
SIG292: PC2.1(A) R38.2 R40.1
SIG294: PC3.5(Vo) R47.1 R49.1
SIG295: D13.C R47.2
SIG296: PC3.1(A) R46.2 R48.1
SIG298: PC5.5(Vo) R60.1 R62.1
SIG299: D15.C R60.2
SIG300: PC5.1(A) R59.2 R61.1
SIG304: PC4.1(A) R51.2 R53.1
SIG305: PC4.5(Vo) R52.1 R54.1
SIG306: D14.C R52.2
SIG308: PC6.1(A) R64.2 R66.1
SIG309: PC6.5(Vo) R65.1 R67.1
SIG310: D16.C R65.2

Not connected (* = marked no-connect by the designer): PC1 2(NC); PC2 2(NC); PC3 2(NC); PC4 2(NC); PC5 2(NC); PC6 2(NC)

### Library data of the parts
C58 C60 C66 C68 C74 C76 = C: OriginalSymbolOrigin: (2540,7620); COMP: C-UMK212B7105KGHT
C59 C61 C67 C69 C75 C77 = C: OriginalSymbolOrigin: (2540,7620); COMP: -C-NC_C1608
D11-D16 = SBD: SAVEAREA0: -4630,-153,17114,13055; TIME: 14:49:55; UPDATEUSER: fukuda-y; UPDATETIME: 08:16:22; SAVECOUNT: 9; OriginalSymbolOrigin: (5080,5080); COMP: -D-CUS10F30_AC
PC1-PC6 = TLP5774: Photocouplers; COMP: PC-TLP5774H_TP4_E; MAKER: TOSHIBA; NOTE: 5kV 8mm; TIME: 11:39:41; UPDATEUSER: t5459927; UPDATETIME: 14:14:00; SAVECOUNT: 2; SAVEAREA0: -5083,-25908,32249,1421; OriginalSymbolOrigin: (0,0)
R33 R38 R46 R51 R59 R64 = R: OriginalSymbolOrigin: (5080,5080); VAL2: 125mW; COMP: -R-RK73H1JTTD6200F
R34 R36 R39 R41 R47 R49 R52 R54 R60 R62 R65 R67 = R: OriginalSymbolOrigin: (5080,5080); VAL2: 250mW; COMP: -R-RK73H2ARTTD10R0F
R35 R40 R48 R53 R61 R66 = R: as R142 on sheet 1
R37 R42 R50 R55 R63 R68 = R: as R140 on sheet 1
TP16-TP19 TP21-TP24 TP26-TP29 = TP: as TP1 on sheet 1
U?#3 = WAKU_DEF100: as U?#1 on sheet 1

## Sheet 4.SchDoc
size 420 x 297 mm
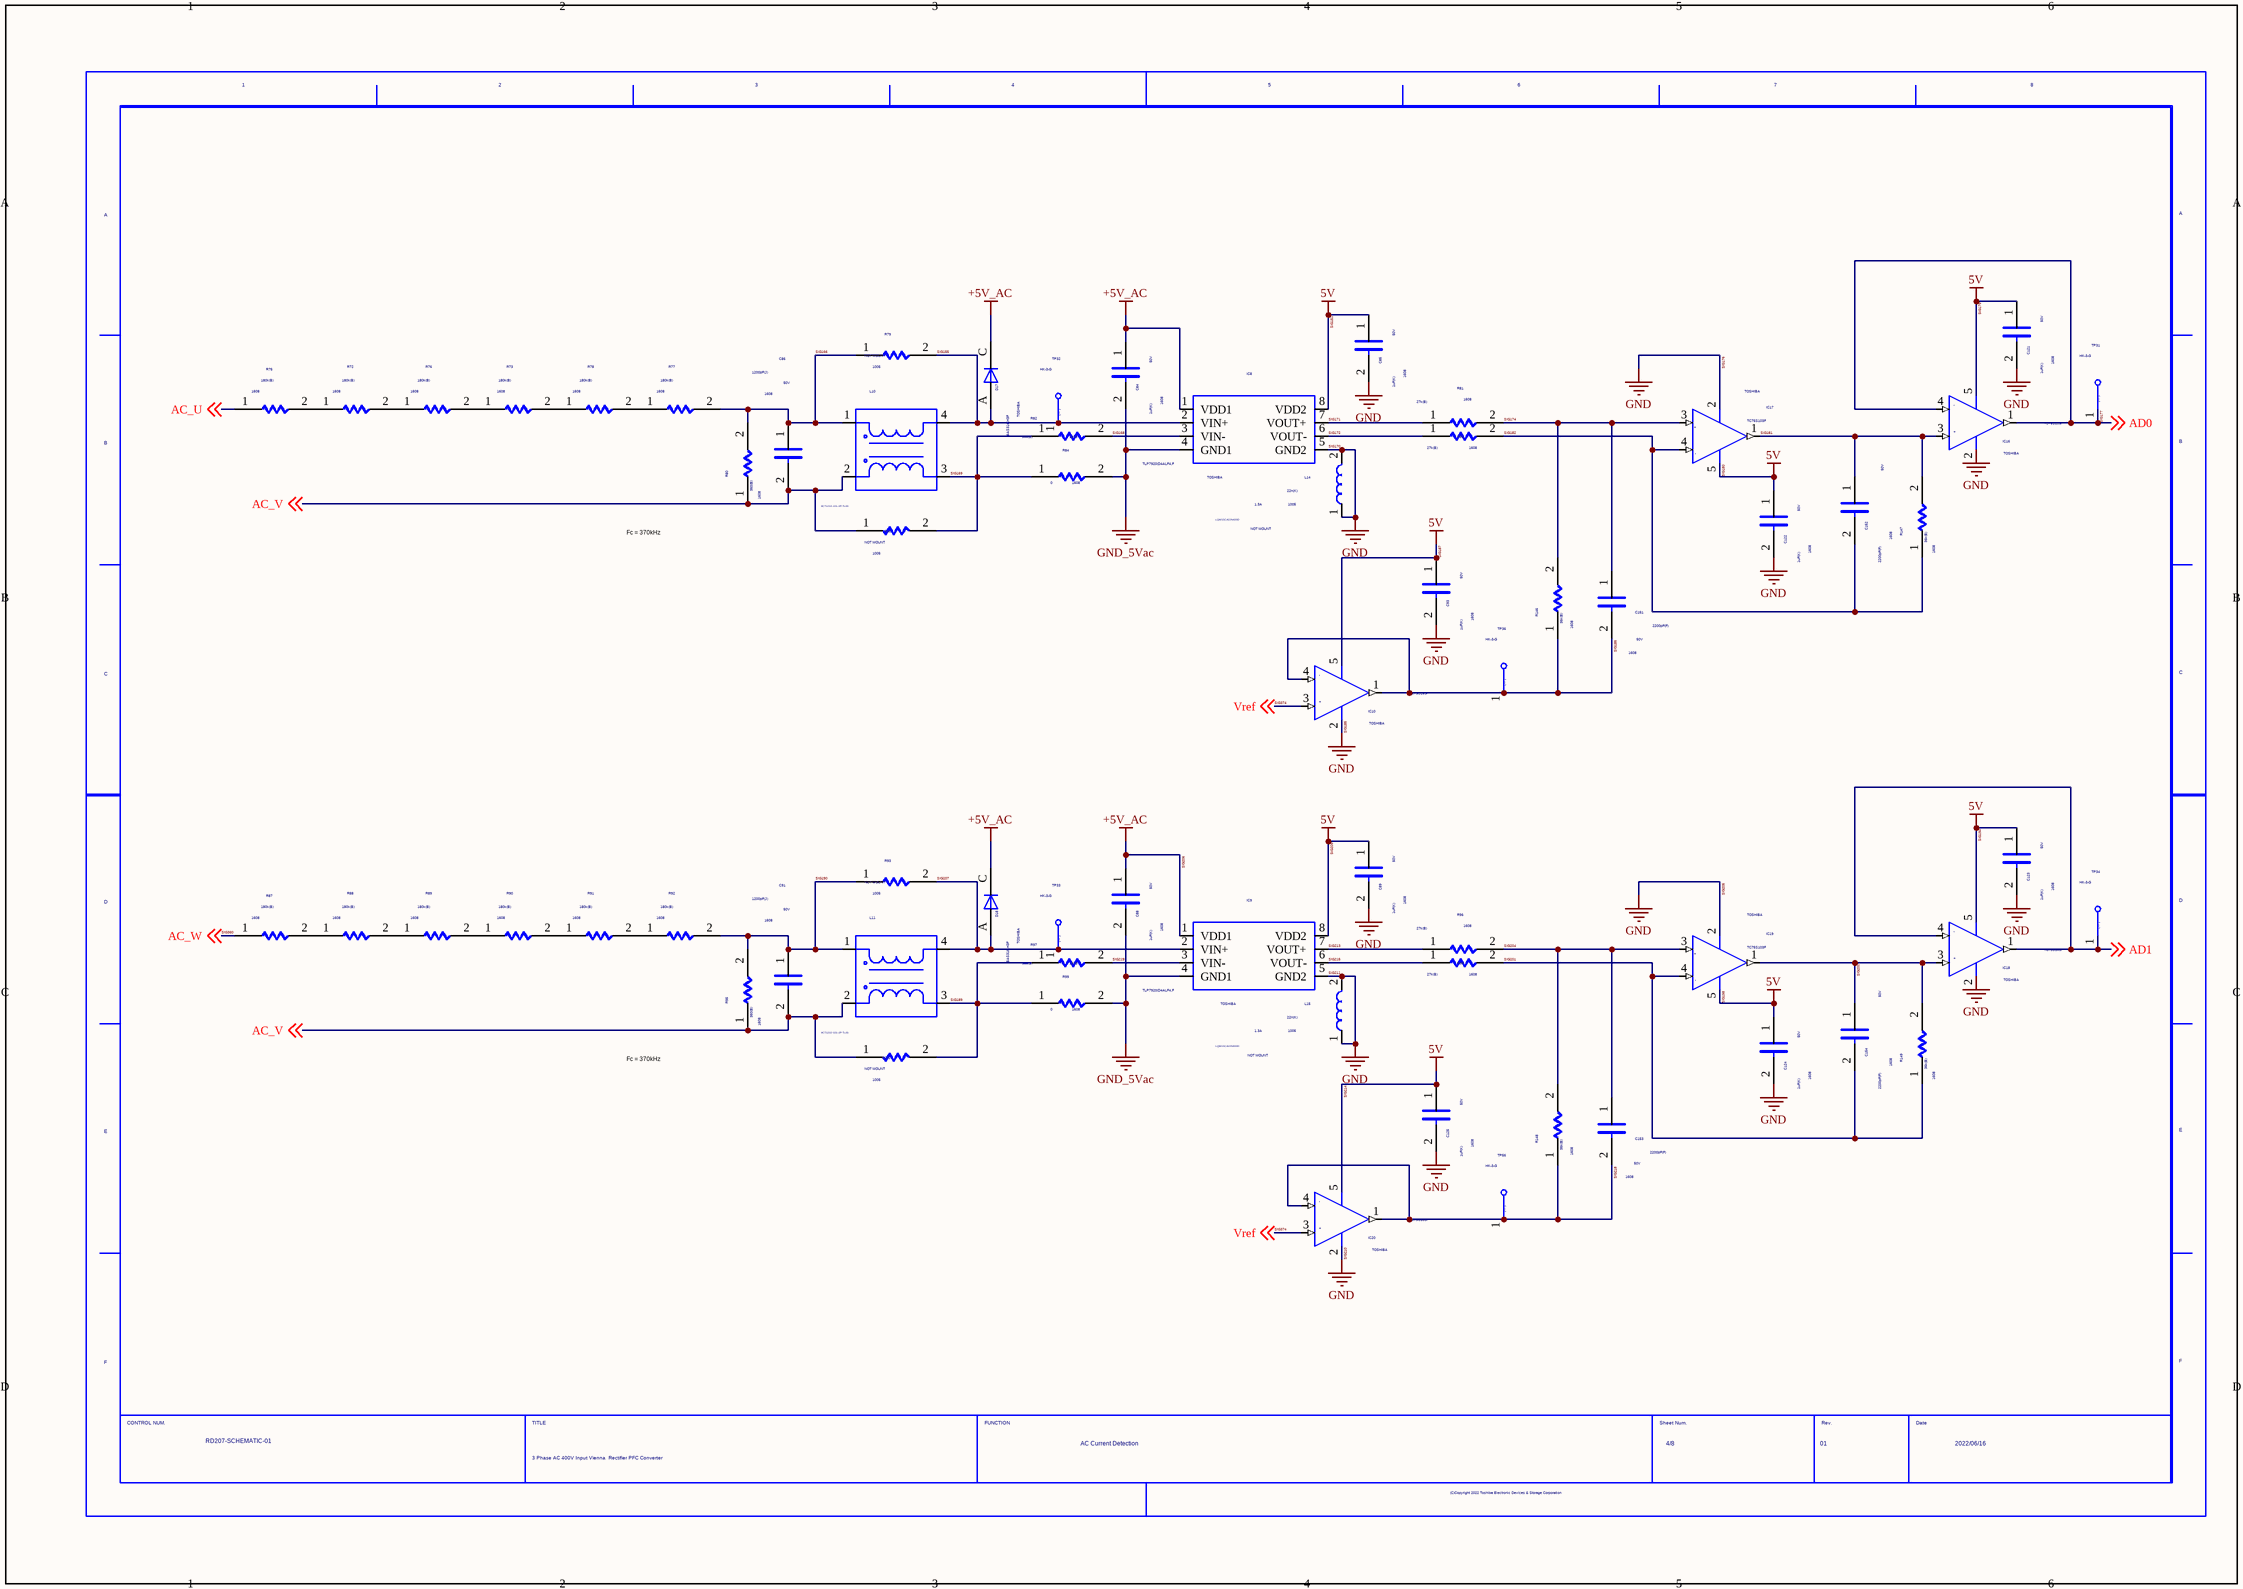
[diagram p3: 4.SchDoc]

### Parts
(Parts that share a designator on the sheet are numbered #1, #2 ... from top to bottom, then left to right.)
C84  SIZECODESMD: 1608  VAL2: 50V  VAL1: 1uF(K)  (hidden comment: C)
C85  SIZECODESMD: 1608  VAL2: 50V  VAL1: 1uF(K)  (hidden comment: C)
C86  SIZECODESMD: 1608  VAL2: 50V  VAL1: 1200pF(J)  (hidden comment: C)
C88  SIZECODESMD: 1608  VAL2: 50V  VAL1: 1uF(K)  (hidden comment: C)
C89  SIZECODESMD: 1608  VAL2: 50V  VAL1: 1uF(K)  (hidden comment: C)
C91  SIZECODESMD: 1608  VAL2: 50V  VAL1: 1200pF(J)  (hidden comment: C)
C93  SIZECODESMD: 1608  VAL2: 50V  VAL1: 1uF(K)  (hidden comment: C)
C121  SIZECODESMD: 1608  VAL2: 50V  VAL1: 1uF(K)  (hidden comment: C)
C122  SIZECODESMD: 1608  VAL2: 50V  VAL1: 1uF(K)  (hidden comment: C)
C123  SIZECODESMD: 1608  VAL2: 50V  VAL1: 1uF(K)  (hidden comment: C)
C124  SIZECODESMD: 1608  VAL2: 50V  VAL1: 1uF(K)  (hidden comment: C)
C125  SIZECODESMD: 1608  VAL2: 50V  VAL1: 1uF(K)  (hidden comment: C)
C151  SIZECODESMD: 1608  VAL2: 50V  VAL1: 2200pF(F)  (hidden comment: C)
C152  SIZECODESMD: 1608  VAL2: 50V  VAL1: 2200pF(F)  (hidden comment: C)
C153  SIZECODESMD: 1608  VAL2: 50V  VAL1: 2200pF(F)  (hidden comment: C)
C154  SIZECODESMD: 1608  VAL2: 50V  VAL1: 2200pF(F)  (hidden comment: C)
D17  USERCOMPTEXT3: TOSHIBA  VAL3: BAS316,H3F  (hidden comment: D)
D18  USERCOMPTEXT3: TOSHIBA  VAL3: BAS316,H3F  (hidden comment: D)
IC8  USERCOMPTEXT3: TOSHIBA  VAL3: TLP7920(D4ALF4,F  (hidden comment: TLP7920(D4ALF1,F)
IC9  USERCOMPTEXT3: TOSHIBA  VAL3: TLP7920(D4ALF4,F  (hidden comment: TLP7920(D4ALF1,F)
IC10  USERCOMPTEXT3: TOSHIBA  (hidden comment: TC75S103F)
IC16  USERCOMPTEXT3: TOSHIBA  (hidden comment: TC75S103F)
IC17  USERCOMPTEXT3: TOSHIBA  (hidden comment: TC75S103F)
IC18  USERCOMPTEXT3: TOSHIBA  (hidden comment: TC75S103F)
IC19  USERCOMPTEXT3: TOSHIBA  (hidden comment: TC75S103F)
IC20  USERCOMPTEXT3: TOSHIBA  (hidden comment: TC75S103F)
L10  ACT1210-101-2P-TL00
L11  ACT1210-101-2P-TL00
L14  NOTMOUNT: NOT MOUNT  VAL3: LQW15CA22NK00D  VAL2: 1.3A  VAL1: 22n(K)  SIZECODESMD: 1005  (hidden comment: L)
L15  NOTMOUNT: NOT MOUNT  VAL3: LQW15CA22NK00D  VAL2: 1.3A  VAL1: 22n(K)  SIZECODESMD: 1005  (hidden comment: L)
R72  SIZECODESMD: 1608  VAL1: 180k(B)  (hidden comment: R)
R73  SIZECODESMD: 1608  VAL1: 180k(B)  (hidden comment: R)
R75  SIZECODESMD: 1608  VAL1: 180k(B)  (hidden comment: R)
R76  SIZECODESMD: 1608  VAL1: 180k(B)  (hidden comment: R)
R77  SIZECODESMD: 1608  VAL1: 180k(B)  (hidden comment: R)
R78  SIZECODESMD: 1608  VAL1: 180k(B)  (hidden comment: R)
R79  SIZECODESMD: 1005  NOTMOUNT: NOT MOUNT  (hidden comment: R)
R80  SIZECODESMD: 1608  VAL1: 360(B)  (hidden comment: R)
R81  SIZECODESMD: 1608  VAL1: 27k(B)  (hidden comment: R)
R82  SIZECODESMD: 1608  VAL1: 360(B)  (hidden comment: R)
R83  SIZECODESMD: 1608  VAL1: 27k(B)  (hidden comment: R)
R84  SIZECODESMD: 1608  VAL1: 0  (hidden comment: R)
R86  SIZECODESMD: 1005  NOTMOUNT: NOT MOUNT  (hidden comment: R)
R87  SIZECODESMD: 1608  VAL1: 180k(B)  (hidden comment: R)
R88  SIZECODESMD: 1608  VAL1: 180k(B)  (hidden comment: R)
R89  SIZECODESMD: 1608  VAL1: 180k(B)  (hidden comment: R)
R90  SIZECODESMD: 1608  VAL1: 180k(B)  (hidden comment: R)
R91  SIZECODESMD: 1608  VAL1: 180k(B)  (hidden comment: R)
R92  SIZECODESMD: 1608  VAL1: 180k(B)  (hidden comment: R)
R93  SIZECODESMD: 1005  NOTMOUNT: NOT MOUNT  (hidden comment: R)
R95  SIZECODESMD: 1608  VAL1: 360(B)  (hidden comment: R)
R96  SIZECODESMD: 1608  VAL1: 27k(B)  (hidden comment: R)
R97  SIZECODESMD: 1608  VAL1: 360(B)  (hidden comment: R)
R98  SIZECODESMD: 1608  VAL1: 27k(B)  (hidden comment: R)
R99  SIZECODESMD: 1608  VAL1: 0  (hidden comment: R)
R101  SIZECODESMD: 1005  NOTMOUNT: NOT MOUNT  (hidden comment: R)
R146  SIZECODESMD: 1608  VAL1: 36k(B)  (hidden comment: R)
R147  SIZECODESMD: 1608  VAL1: 36k(B)  (hidden comment: R)
R148  SIZECODESMD: 1608  VAL1: 36k(B)  (hidden comment: R)
R149  SIZECODESMD: 1608  VAL1: 36k(B)  (hidden comment: R)
TP31  VAL3: HK-3-G  (hidden comment: TP)
TP32  VAL3: HK-3-G  (hidden comment: TP)
TP33  VAL3: HK-3-G  (hidden comment: TP)
TP34  VAL3: HK-3-G  (hidden comment: TP)
TP36  VAL3: HK-3-G  (hidden comment: TP)
TP56  VAL3: HK-3-G  (hidden comment: TP)
U?#4  DATE: 2022/06/16  TITLE: 3 Phase AC 400V Input Vienna / Rectifier PFC Converter  REVISION: 01  SHEETNUMBER: 4/8  FUNCTION: AC Current Detection  DRAWINGNUMBER: RD207-SCHEMATIC-01  (hidden comment: WAKU_DEF100)

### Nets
5V: C85.1 C89.1 C93.1 C121.1 C122.1 C123.1 C124.1 C125.1 IC8.8(VDD2) IC9.8(VDD2) IC10.5 IC16.5 IC17.5 IC18.5 IC19.5 IC20.5  [also labelled SIG151, SIG179, SIG180, SIG187, SIG194, SIG198, SIG209, SIG214]  [project net SIG104]
GND: C85.2 C89.2 C93.2 C121.2 C122.2 C123.2 C124.2 C125.2 IC8.5(GND2) IC9.5(GND2) IC10.2 IC16.2 IC17.2 IC18.2 IC19.2 IC20.2 L14.1 L14.2 L15.1 L15.2  [also labelled SIG170, SIG176, SIG185, SIG205, SIG210, SIG211]  [project net SIG105]
GND_5Vac: C84.2 C88.2 IC8.4(GND1) IC9.4(GND1) R84.2 R99.2
SIG153: C84.1 C88.1 D17.C D18.C IC8.1(VDD1) IC9.1(VDD1)  [also labelled +5V_AC, SIG159, SIG192, SIG206]
AC_U: R75.1 ; off-sheet AC_U
AC_V: C86.2 C91.2 L10.2 L11.2 R80.1 R86.1 R95.1 R101.1 ; off-sheet AC_V
AD1: IC18.1 IC18.4 TP34.1 ; off-sheet AD1
SIG155: D17.A IC8.2(VIN+) L10.4 R79.2 TP32.1
SIG166: C86.1 L10.1 R77.2 R79.1 R80.2
SIG168: IC8.3(VIN-) R82.2
SIG169: L10.3 R82.1 R84.1 R86.2
SIG171: IC8.7(VOUT+) R81.1
SIG172: IC8.6(VOUT-) R83.1
SIG174: C151.1 IC17.3 R81.2 R146.2
SIG177: IC16.1 IC16.4 TP31.1 ; off-sheet AD0  [also labelled AD0]
SIG181: C152.1 IC16.3 IC17.1 R147.2
SIG182: C152.2 IC17.4 R83.2 R147.1
SIG186: C151.2 IC10.1 IC10.4 R146.1 TP36.1
SIG189: L11.3 R97.1 R99.1 R101.2
SIG190: C91.1 L11.1 R92.2 R93.1 R95.2
SIG200: C154.1 IC18.3 IC19.1 R149.2
SIG201: C154.2 IC19.4 R98.2 R149.1
SIG204: C153.1 IC19.3 R96.2 R148.2
SIG207: D18.A IC9.2(VIN+) L11.4 R93.2 TP33.1
SIG213: IC9.7(VOUT+) R96.1
SIG215: IC9.6(VOUT-) R98.1
SIG218: C153.2 IC20.1 IC20.4 R148.1 TP56.1
SIG219: IC9.3(VIN-) R97.2
SIG360: R87.1 ; off-sheet AC_W  [also labelled AC_W]
SIG374: IC10.3 IC20.3 ; off-sheet Vref  [also labelled Vref]
NetR72_1: R72.1 R75.2
NetR72_2: R72.2 R76.1
NetR73_1: R73.1 R76.2
NetR73_2: R73.2 R78.1
NetR77_1: R77.1 R78.2
NetR87_2: R87.2 R88.1
NetR88_2: R88.2 R89.1
NetR89_2: R89.2 R90.1
NetR90_2: R90.2 R91.1
NetR91_2: R91.2 R92.1

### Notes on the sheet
- Fc = 370kHz

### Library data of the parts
C84 C85 C88 C89 C93 C121-C125 = C: as C1 on sheet 1
C86 C91 = C: OriginalSymbolOrigin: (2540,7620); COMP: -C-GRM1885C1H122JA01J
C151-C154 = C: OriginalSymbolOrigin: (2540,7620); COMP: -C-GCM1885C1H222FA16D
D17 D18 = D: as D1 on sheet 1
IC8 IC9 = TLP7920_D4ALF4_F: Photocoupler; COMP: IC-TLP7920F_D4ALF4_F; TIME: 16:53:58; UPDATEUSER: t5459927; UPDATETIME: 15:20:44; SAVECOUNT: 3; SAVEAREA0: -6054,-17255,23482,4367; OriginalSymbolOrigin: (0,0)
IC10 IC16-IC20 = TC75S103F: COMP: IC-TC75S103F; TIME: 16:31:59; UPDATEUSER: t5459927; UPDATETIME: 13:42:20; SAVECOUNT: 13; SAVEAREA0: 0,-513,15240,10643; OriginalSymbolOrigin: (2540,10160)
L10 L11 = ACT1210_101_2P_TL00: 150mA; MAKER: TDK; COMP: -L-ACT1210-101-2P-TL00; NOTE: 100uH; TIME: 11:39:41; UPDATEUSER: t5459927; UPDATETIME: 16:14:20; SAVECOUNT: 2; SAVEAREA0: -3836,-15544,18561,852; OriginalSymbolOrigin: (0,0); VAL1: 100uH(Z)
L14 L15 = L: OriginalSymbolOrigin: (2540,5080); COMP: L-NC_LQW15CA22NK00D
R72 R73 R75-R78 R87-R92 = R: OriginalSymbolOrigin: (5080,5080); COMP: -R-ERA3AEB184V; VAL2: 100mW
R79 R86 R93 R101 = R: OriginalSymbolOrigin: (5080,5080); COMP: -R-NC_R1005
R80 R82 R95 R97 = R: OriginalSymbolOrigin: (5080,5080); COMP: -R-ERA3AEB361V; VAL2: 100mW
R81 R83 R96 R98 = R: OriginalSymbolOrigin: (5080,5080); COMP: -R-ERA3AEB273V; VAL2: 100mW
R84 R99 = R: OriginalSymbolOrigin: (5080,5080); COMP: -R-RK73Z1JTTD; VAL2: 1A
R146-R149 = R: OriginalSymbolOrigin: (5080,5080); COMP: -R-ERA3ARB363V; VAL2: 100mW
TP31-TP34 TP36 TP56 = TP: as TP1 on sheet 1
U?#4 = WAKU_DEF100: as U?#1 on sheet 1

## Sheet 5.SchDoc
size 420 x 297 mm
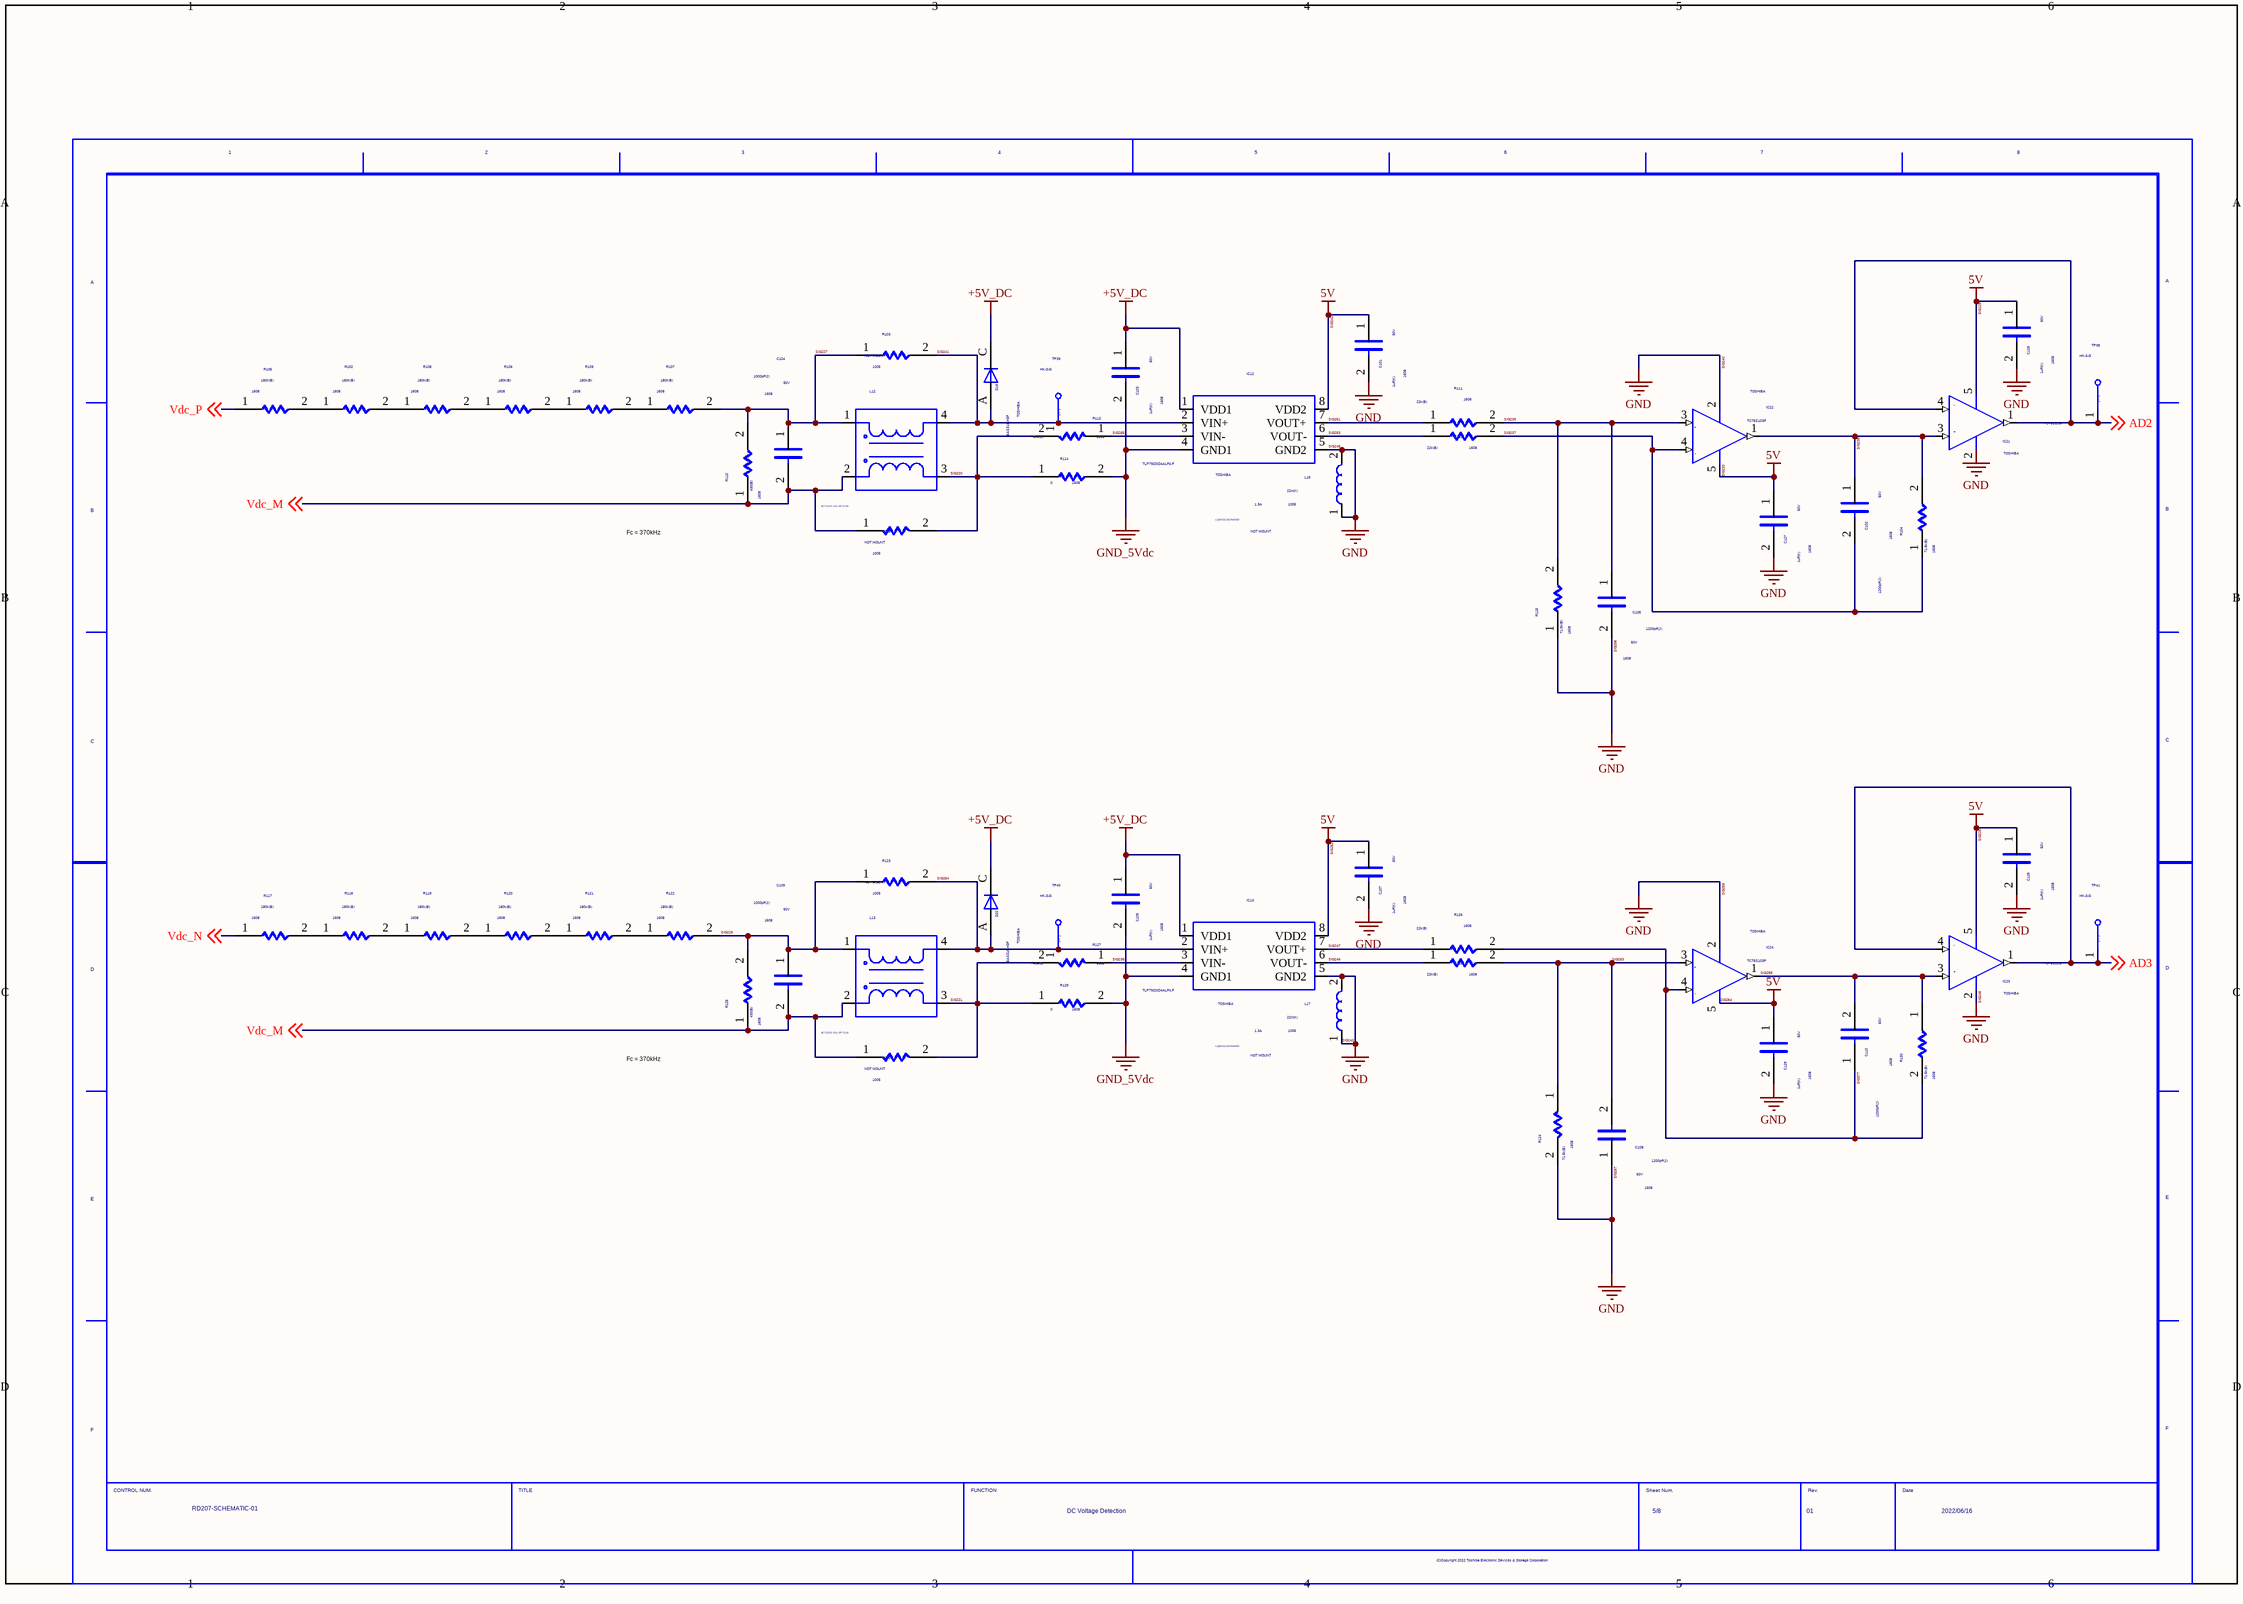
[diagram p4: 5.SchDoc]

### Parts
(Parts that share a designator on the sheet are numbered #1, #2 ... from top to bottom, then left to right.)
C101  SIZECODESMD: 1608  VAL2: 50V  VAL1: 1uF(K)  (hidden comment: C)
C102  SIZECODESMD: 1608  VAL2: 50V  VAL1: 1200pF(J)  (hidden comment: C)
C103  SIZECODESMD: 1608  VAL2: 50V  VAL1: 1uF(K)  (hidden comment: C)
C104  SIZECODESMD: 1608  VAL2: 50V  VAL1: 1000pF(J)  (hidden comment: C)
C105  SIZECODESMD: 1608  VAL2: 50V  VAL1: 1200pF(J)  (hidden comment: C)
C106  SIZECODESMD: 1608  VAL2: 50V  VAL1: 1uF(K)  (hidden comment: C)
C107  SIZECODESMD: 1608  VAL2: 50V  VAL1: 1uF(K)  (hidden comment: C)
C108  SIZECODESMD: 1608  VAL2: 50V  VAL1: 1200pF(J)  (hidden comment: C)
C109  SIZECODESMD: 1608  VAL2: 50V  VAL1: 1000pF(J)  (hidden comment: C)
C110  SIZECODESMD: 1608  VAL2: 50V  VAL1: 1200pF(J)  (hidden comment: C)
C126  SIZECODESMD: 1608  VAL2: 50V  VAL1: 1uF(K)  (hidden comment: C)
C127  SIZECODESMD: 1608  VAL2: 50V  VAL1: 1uF(K)  (hidden comment: C)
C128  SIZECODESMD: 1608  VAL2: 50V  VAL1: 1uF(K)  (hidden comment: C)
C129  SIZECODESMD: 1608  VAL2: 50V  VAL1: 1uF(K)  (hidden comment: C)
D19  USERCOMPTEXT3: TOSHIBA  VAL3: BAS316,H3F  (hidden comment: D)
D20  USERCOMPTEXT3: TOSHIBA  VAL3: BAS316,H3F  (hidden comment: D)
IC12  USERCOMPTEXT3: TOSHIBA  VAL3: TLP7920(D4ALF4,F  (hidden comment: TLP7920(D4ALF1,F)
IC13  USERCOMPTEXT3: TOSHIBA  VAL3: TLP7920(D4ALF4,F  (hidden comment: TLP7920(D4ALF1,F)
IC21  USERCOMPTEXT3: TOSHIBA  (hidden comment: TC75S103F)
IC22  USERCOMPTEXT3: TOSHIBA  (hidden comment: TC75S103F)
IC23  USERCOMPTEXT3: TOSHIBA  (hidden comment: TC75S103F)
IC24  USERCOMPTEXT3: TOSHIBA  (hidden comment: TC75S103F)
L12  ACT1210-101-2P-TL00
L13  ACT1210-101-2P-TL00
L16  NOTMOUNT: NOT MOUNT  VAL3: LQW15CA22NK00D  VAL2: 1.3A  VAL1: 22n(K)  SIZECODESMD: 1005  (hidden comment: L)
L17  NOTMOUNT: NOT MOUNT  VAL3: LQW15CA22NK00D  VAL2: 1.3A  VAL1: 22n(K)  SIZECODESMD: 1005  (hidden comment: L)
R102  SIZECODESMD: 1608  VAL1: 180k(B)  (hidden comment: R)
R103  SIZECODESMD: 1005  NOTMOUNT: NOT MOUNT  (hidden comment: R)
R104  SIZECODESMD: 1608  VAL1: 71.5k(B)  (hidden comment: R)
R105  SIZECODESMD: 1608  VAL1: 180k(B)  (hidden comment: R)
R106  SIZECODESMD: 1608  VAL1: 180k(B)  (hidden comment: R)
R107  SIZECODESMD: 1608  VAL1: 180k(B)  (hidden comment: R)
R108  SIZECODESMD: 1608  VAL1: 180k(B)  (hidden comment: R)
R109  SIZECODESMD: 1608  VAL1: 180k(B)  (hidden comment: R)
R110  SIZECODESMD: 1608  VAL1: 430(B)  (hidden comment: R)
R111  SIZECODESMD: 1608  VAL1: 22k(B)  (hidden comment: R)
R112  SIZECODESMD: 1608  VAL1: 430(B)  (hidden comment: R)
R113  SIZECODESMD: 1608  VAL1: 22k(B)  (hidden comment: R)
R114  SIZECODESMD: 1608  VAL1: 0  (hidden comment: R)
R115  SIZECODESMD: 1608  VAL1: 71.5k(B)  (hidden comment: R)
R116  SIZECODESMD: 1005  NOTMOUNT: NOT MOUNT  (hidden comment: R)
R117  SIZECODESMD: 1608  VAL1: 180k(B)  (hidden comment: R)
R118  SIZECODESMD: 1608  VAL1: 180k(B)  (hidden comment: R)
R119  SIZECODESMD: 1608  VAL1: 180k(B)  (hidden comment: R)
R120  SIZECODESMD: 1608  VAL1: 180k(B)  (hidden comment: R)
R121  SIZECODESMD: 1608  VAL1: 180k(B)  (hidden comment: R)
R122  SIZECODESMD: 1608  VAL1: 180k(B)  (hidden comment: R)
R123  SIZECODESMD: 1005  NOTMOUNT: NOT MOUNT  (hidden comment: R)
R124  SIZECODESMD: 1608  VAL1: 71.5k(B)  (hidden comment: R)
R125  SIZECODESMD: 1608  VAL1: 430(B)  (hidden comment: R)
R126  SIZECODESMD: 1608  VAL1: 22k(B)  (hidden comment: R)
R127  SIZECODESMD: 1608  VAL1: 430(B)  (hidden comment: R)
R128  SIZECODESMD: 1608  VAL1: 22k(B)  (hidden comment: R)
R129  SIZECODESMD: 1608  VAL1: 0  (hidden comment: R)
R130  SIZECODESMD: 1608  VAL1: 71.5k(B)  (hidden comment: R)
R131  SIZECODESMD: 1005  NOTMOUNT: NOT MOUNT  (hidden comment: R)
TP38  VAL3: HK-3-G  (hidden comment: TP)
TP39  VAL3: HK-3-G  (hidden comment: TP)
TP40  VAL3: HK-3-G  (hidden comment: TP)
TP41  VAL3: HK-3-G  (hidden comment: TP)
U?#5  DATE: 2022/06/16  REVISION: 01  SHEETNUMBER: 5/8  FUNCTION: DC Voltage Detection  DRAWINGNUMBER: RD207-SCHEMATIC-01  (hidden comment: WAKU_DEF100)

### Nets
5V: C101.1 C107.1 C126.1 C127.1 C128.1 C129.1 IC12.8(VDD2) IC13.8(VDD2) IC21.5 IC22.5 IC23.5 IC24.5  [also labelled SIG225, SIG229, SIG233, SIG242, SIG252, SIG264]  [project net SIG104]
+5V_DC: C103.1 C106.1 D19.C D20.C IC12.1(VDD1) IC13.1(VDD1)
GND: C101.2 C105.2 C107.2 C108.1 C126.2 C127.2 C128.2 C129.2 IC12.5(GND2) IC13.5(GND2) IC21.2 IC22.2 IC23.2 IC24.2 L16.1 L16.2 L17.1 L17.2 R115.1 R124.2  [also labelled SIG240, SIG243, SIG245, SIG248, SIG259, SIG266, SIG267]  [project net SIG105]
GND_5Vdc: C103.2 C106.2 IC12.4(GND1) IC13.4(GND1) R114.2 R129.2
AD2: IC21.1 IC21.4 TP38.1 ; off-sheet AD2
AD3: IC23.1 IC23.4 TP41.1 ; off-sheet AD3
SIG220: L12.3 R112.2 R114.1 R116.2
SIG221: L13.3 R127.2 R129.1 R131.2
SIG226: C109.1 L13.1 R122.2 R123.1 R125.2
SIG227: C104.1 L12.1 R103.1 R107.2 R110.2
SIG235: C102.1 IC21.3 IC22.1 R104.2
SIG236: IC13.3(VIN-) R127.1
SIG237: C102.2 IC22.4 R104.1 R113.2
SIG239: C105.1 IC22.3 R111.2 R115.2
SIG241: D19.A IC12.2(VIN+) L12.4 R103.2 TP39.1
SIG246: IC13.6(VOUT-) R128.1
SIG247: IC13.7(VOUT+) R126.1
SIG251: IC12.7(VOUT+) R111.1
SIG253: IC12.6(VOUT-) R113.1
SIG254: D20.A IC13.2(VIN+) L13.4 R123.2 TP40.1
SIG255: C110.2 IC23.3 IC24.1 R130.1
SIG263: C108.2 IC24.3 R124.1 R128.2
SIG265: IC12.3(VIN-) R112.1
SIG377: C110.1 IC24.4 R126.2 R130.2
Vdc_M: C104.2 C109.2 L12.2 L13.2 R110.1 R116.1 R125.1 R131.1 ; off-sheet Vdc_M
Vdc_N: R117.1 ; off-sheet Vdc_N
Vdc_P: R105.1 ; off-sheet Vdc_P
NetR102_1: R102.1 R105.2
NetR102_2: R102.2 R108.1
NetR106_1: R106.1 R108.2
NetR106_2: R106.2 R109.1
NetR107_1: R107.1 R109.2
NetR117_2: R117.2 R118.1
NetR118_2: R118.2 R119.1
NetR119_2: R119.2 R120.1
NetR120_2: R120.2 R121.1
NetR121_2: R121.2 R122.1

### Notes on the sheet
- Fc = 370kHz

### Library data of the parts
C101 C103 C106 C107 C126-C129 = C: as C1 on sheet 1
C102 C105 C108 = C: as C86 on sheet 4
C104 C109 = C: OriginalSymbolOrigin: (2540,7620); COMP: -C-GRM1885C1H102JA01D
C110 = C#1: OriginalSymbolOrigin: (2540,7620); CaptureCellPackProp: C##1; COMP: -C-GRM1885C1H122JA01J
D19 D20 = D: as D1 on sheet 1
IC12 IC13 = TLP7920_D4ALF4_F: as IC8 on sheet 4
IC21-IC24 = TC75S103F: as IC10 on sheet 4
L12 L13 = ACT1210_101_2P_TL00: as L10 on sheet 4
L16 L17 = L: as L14 on sheet 4
R102 R105-R109 R117-R122 = R: as R72 on sheet 4
R103 R116 R123 R131 = R: as R79 on sheet 4
R104 R115 R124 = R: OriginalSymbolOrigin: (5080,5080); COMP: -R-ERA3AEB7152V; VAL2: 100mW
R110 R112 R125 R127 = R: OriginalSymbolOrigin: (5080,5080); COMP: -R-ERA3AEB431V; VAL2: 100mW
R111 R113 R126 R128 = R: OriginalSymbolOrigin: (5080,5080); COMP: -R-ERA3AEB223V; VAL2: 100mW
R114 R129 = R: as R84 on sheet 4
R130 = R#1: OriginalSymbolOrigin: (5080,5080); CaptureCellPackProp: R##1; COMP: -R-ERA3AEB7152V; VAL2: 100mW
TP38-TP41 = TP: as TP1 on sheet 1
U?#5 = WAKU_DEF100: as U?#1 on sheet 1

## Sheet 6.SchDoc
size 420 x 297 mm
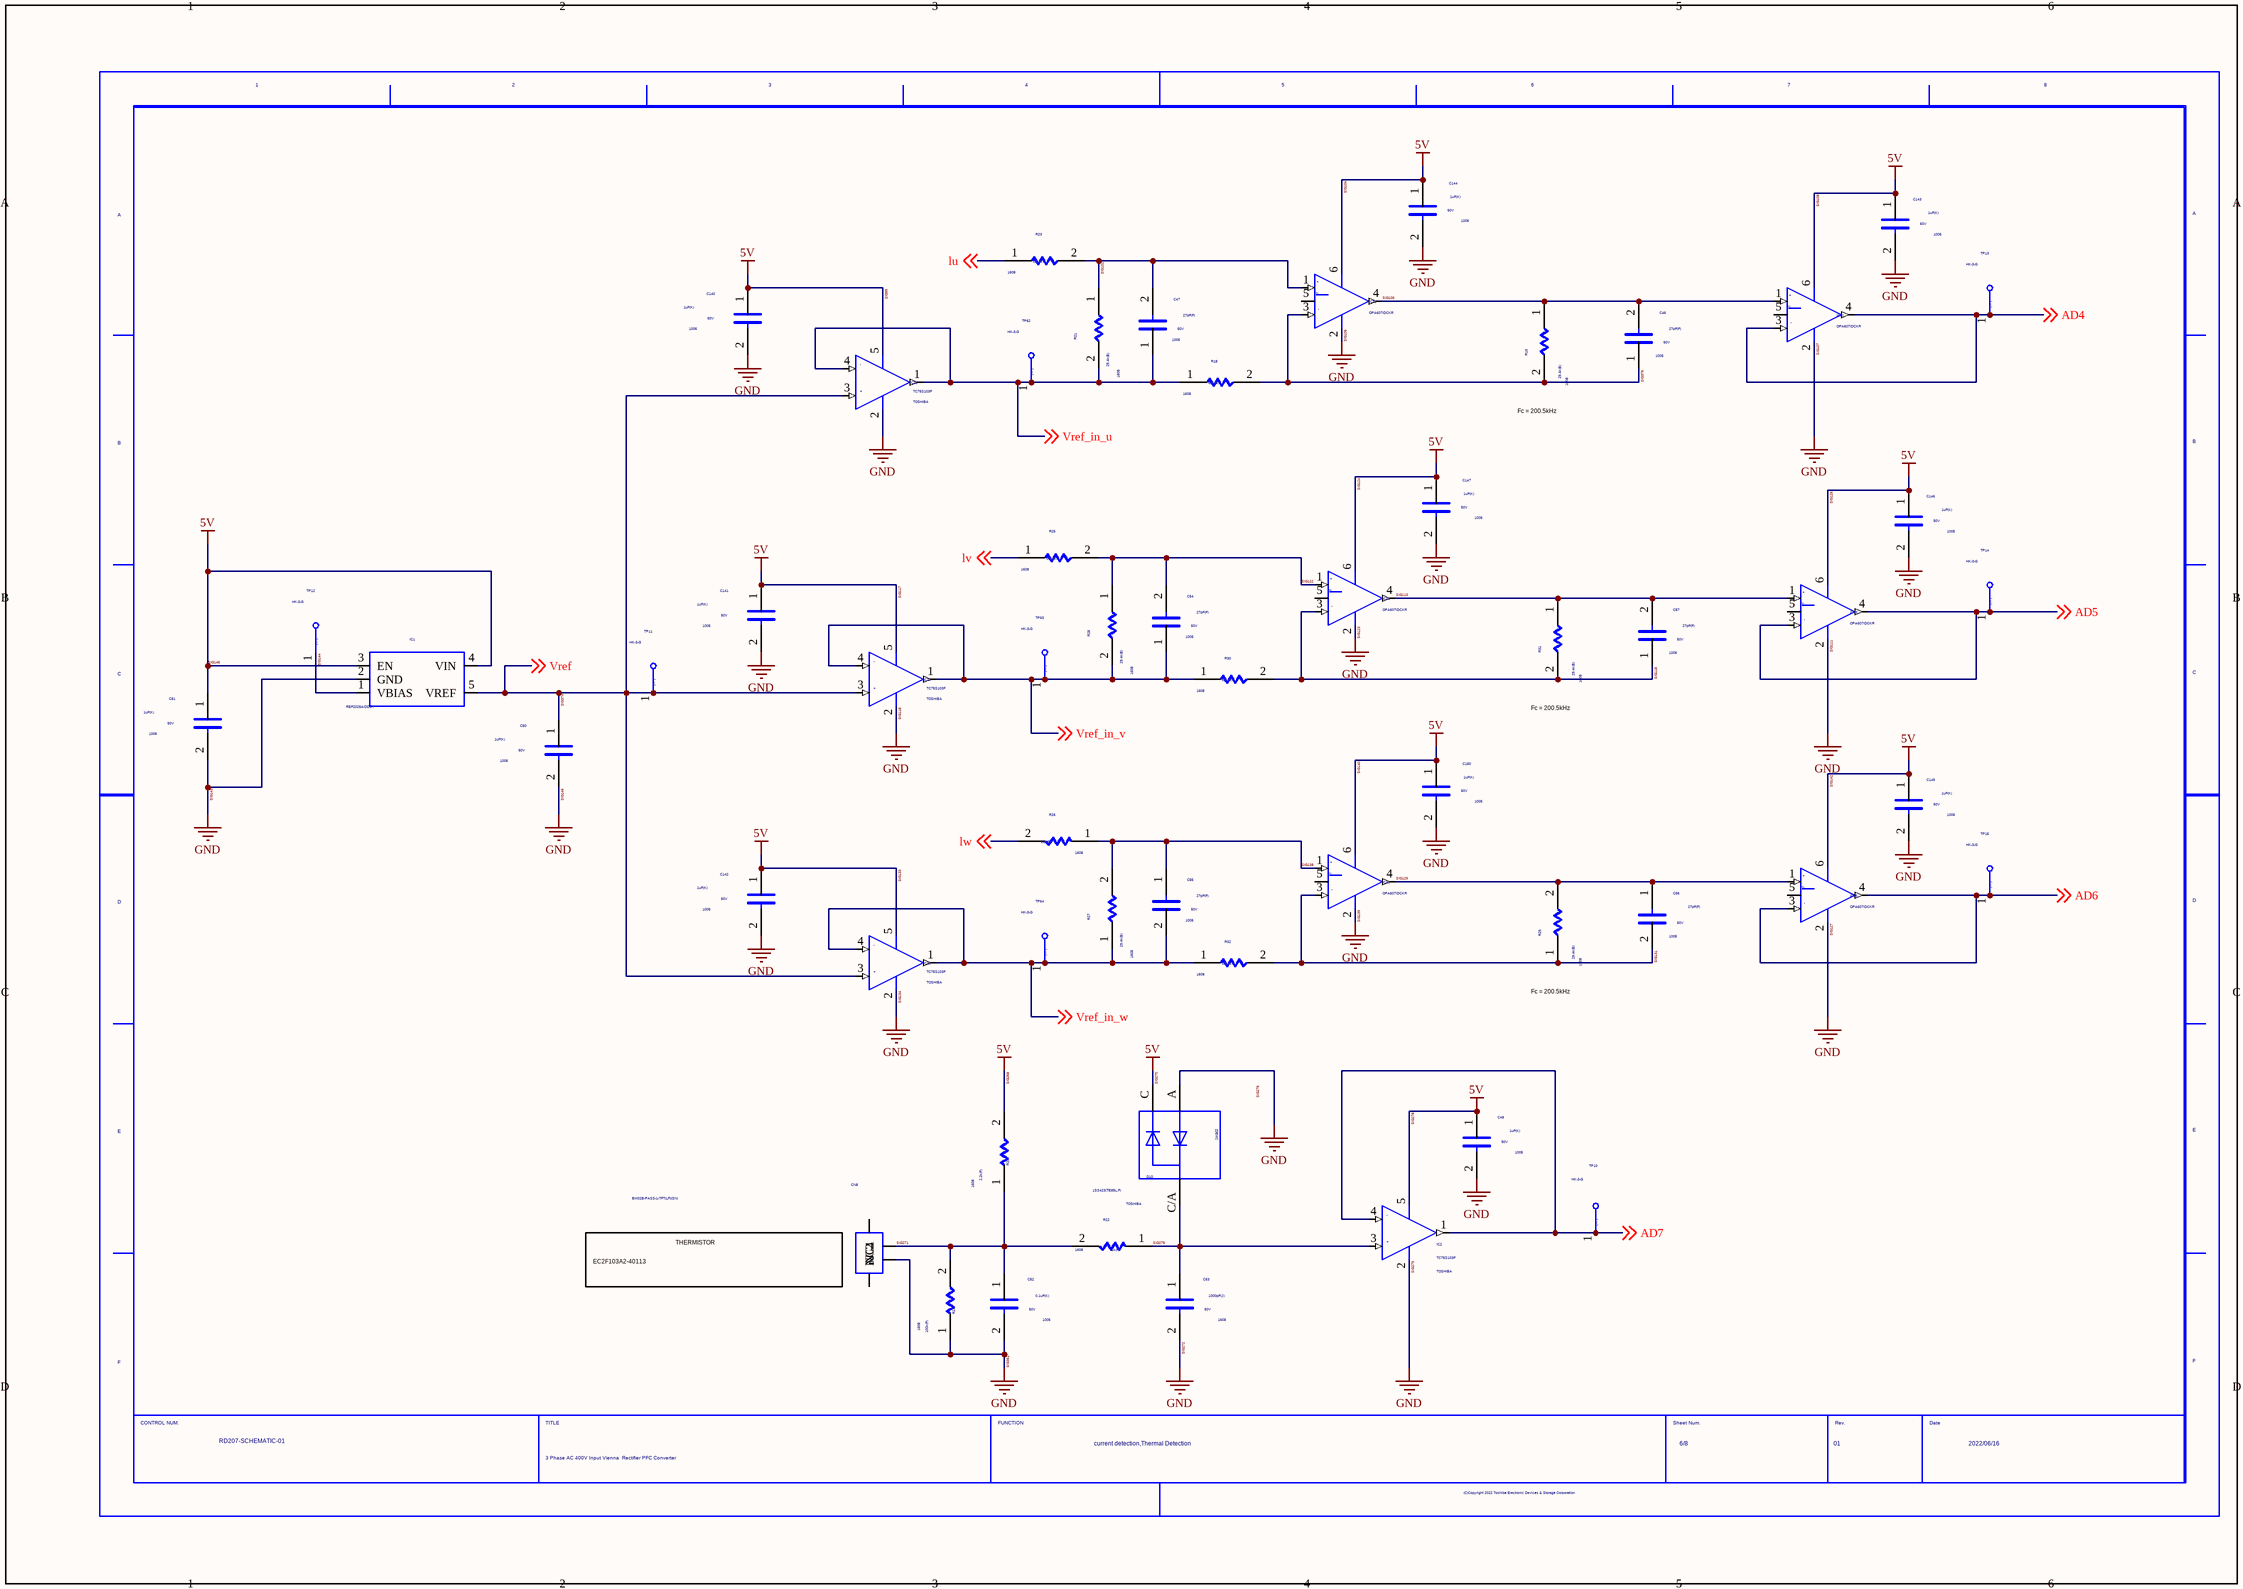
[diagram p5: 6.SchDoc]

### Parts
(Parts that share a designator on the sheet are numbered #1, #2 ... from top to bottom, then left to right.)
C46  SIZECODESMD: 1005  VAL2: 50V  VAL1: 27pF(F)  (hidden comment: C)
C47  SIZECODESMD: 1005  VAL2: 50V  VAL1: 27pF(F)  (hidden comment: C)
C48  SIZECODESMD: 1005  VAL2: 50V  VAL1: 1uF(K)  (hidden comment: C)
C50  SIZECODESMD: 1005  VAL2: 50V  VAL1: 1uF(K)  (hidden comment: C)
C51  SIZECODESMD: 1005  VAL2: 50V  VAL1: 1uF(K)  (hidden comment: C)
C52  SIZECODESMD: 1005  VAL2: 50V  VAL1: 0.1uF(K)  (hidden comment: C)
C53  SIZECODESMD: 1608  VAL2: 50V  VAL1: 1000pF(J)  (hidden comment: C)
C54  SIZECODESMD: 1005  VAL2: 50V  VAL1: 27pF(F)  (hidden comment: C)
C55  SIZECODESMD: 1005  VAL2: 50V  VAL1: 27pF(F)  (hidden comment: C)
C56  SIZECODESMD: 1005  VAL2: 50V  VAL1: 27pF(F)  (hidden comment: C)
C57  SIZECODESMD: 1005  VAL2: 50V  VAL1: 27pF(F)  (hidden comment: C)
C140  SIZECODESMD: 1005  VAL2: 50V  VAL1: 1uF(K)  (hidden comment: C)
C141  SIZECODESMD: 1005  VAL2: 50V  VAL1: 1uF(K)  (hidden comment: C)
C142  SIZECODESMD: 1005  VAL2: 50V  VAL1: 1uF(K)  (hidden comment: C)
C143  SIZECODESMD: 1005  VAL2: 50V  VAL1: 1uF(K)  (hidden comment: C)
C144  SIZECODESMD: 1005  VAL2: 50V  VAL1: 1uF(K)  (hidden comment: C)
C146  SIZECODESMD: 1005  VAL2: 50V  VAL1: 1uF(K)  (hidden comment: C)
C147  SIZECODESMD: 1005  VAL2: 50V  VAL1: 1uF(K)  (hidden comment: C)
C149  SIZECODESMD: 1005  VAL2: 50V  VAL1: 1uF(K)  (hidden comment: C)
C150  SIZECODESMD: 1005  VAL2: 50V  VAL1: 1uF(K)  (hidden comment: C)
CN8  BM02B-PASS-1-TFT(LF)(SN)
D10  USERCOMPTEXT3: TOSHIBA  VAL3: 1SS423(TE85L,F)  (hidden comment: DEW)
IC1  REF2025AIDDCT
IC2  USERCOMPTEXT3: TOSHIBA  (hidden comment: TC75S103F)
IC28  USERCOMPTEXT3: TOSHIBA  (hidden comment: TC75S103F)
IC29  USERCOMPTEXT3: TOSHIBA  (hidden comment: TC75S103F)
IC30  USERCOMPTEXT3: TOSHIBA  (hidden comment: TC75S103F)
IC31  OPA607IDCKR
IC32  OPA607IDCKR
IC33  OPA607IDCKR
IC34  OPA607IDCKR
IC35  OPA607IDCKR
IC36  OPA607IDCKR
R18  SIZECODESMD: 1608  VAL1: 22k(B)  (hidden comment: R)
R19  SIZECODESMD: 1608  VAL1: 29.4k(B)  (hidden comment: R)
R20  SIZECODESMD: 1608  VAL1: 2.2k(F)  (hidden comment: R)
R21  SIZECODESMD: 1608  VAL1: 29.4k(B)  (hidden comment: R)
R22  SIZECODESMD: 1608  VAL1: 1k(F)  (hidden comment: R)
R23  SIZECODESMD: 1608  VAL1: 22k(B)  (hidden comment: R)
R24  SIZECODESMD: 1608  VAL1: 100k(F)  (hidden comment: R)
R25  SIZECODESMD: 1608  VAL1: 22k(B)  (hidden comment: R)
R26  SIZECODESMD: 1608  VAL1: 22k(B)  (hidden comment: R)
R27  SIZECODESMD: 1608  VAL1: 29.4k(B)  (hidden comment: R)
R28  SIZECODESMD: 1608  VAL1: 29.4k(B)  (hidden comment: R)
R29  SIZECODESMD: 1608  VAL1: 29.4k(B)  (hidden comment: R)
R30  SIZECODESMD: 1608  VAL1: 22k(B)  (hidden comment: R)
R31  SIZECODESMD: 1608  VAL1: 29.4k(B)  (hidden comment: R)
R32  SIZECODESMD: 1608  VAL1: 22k(B)  (hidden comment: R)
TP10  VAL3: HK-3-G  (hidden comment: TP)
TP11  VAL3: HK-3-G  (hidden comment: TP)
TP12  VAL3: HK-3-G  (hidden comment: TP)
TP13  VAL3: HK-3-G  (hidden comment: TP)
TP14  VAL3: HK-3-G  (hidden comment: TP)
TP15  VAL3: HK-3-G  (hidden comment: TP)
TP62  VAL3: HK-3-G  (hidden comment: TP)
TP63  VAL3: HK-3-G  (hidden comment: TP)
TP64  VAL3: HK-3-G  (hidden comment: TP)
U?#6  DATE: 2022/06/16  TITLE: 3 Phase AC 400V Input Vienna / Rectifier PFC Converter  REVISION: 01  SHEETNUMBER: 6/8  FUNCTION: current detection,Thermal Detection  DRAWINGNUMBER: RD207-SCHEMATIC-01  (hidden comment: WAKU_DEF100)

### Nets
SIG104: C48.1 C51.1 C140.1 C141.1 C142.1 C143.1 C144.1 C146.1 C147.1 C149.1 C150.1 D10.C IC1.3(EN) IC1.4(VIN) IC2.5 IC28.5 IC29.5 IC30.5 IC31.6 IC32.6 IC33.6 IC34.6 IC35.6 IC36.6 R20.2  [also labelled 5V, SIG108, SIG117, SIG124, SIG126, SIG133, SIG140, SIG142, SIG145, SIG268, SIG270, SIG278, SIG99]
SIG105: C48.2 C50.2 C51.2 C52.2 C53.2 C140.2 C141.2 C142.2 C143.2 C144.2 C146.2 C147.2 C149.2 C150.2 CN8.2 D10.A IC1.2(GND) IC2.2 IC28.2 IC29.2 IC30.2 IC31.2 IC32.2 IC33.2 IC34.2 IC35.2 IC36.2 R24.1  [also labelled GND, SIG107, SIG111, SIG118, SIG123, SIG127, SIG134, SIG139, SIG143, SIG146, SIG272, SIG279, SIG361]
AD4: IC31.3 IC31.4 TP13.1 ; off-sheet AD4
AD5: IC33.3 IC33.4 TP14.1 ; off-sheet AD5
AD6: IC35.3 IC35.4 TP15.1 ; off-sheet AD6
AD7: IC2.1 IC2.4 TP10.1 ; off-sheet AD7
lu: R23.1 ; off-sheet lu
lv: R25.1 ; off-sheet lv
lw: R26.2 ; off-sheet lw
SIG101: C47.2 IC32.1 R21.1 R23.2
SIG106: C46.2 IC31.1 IC32.4 R19.1
SIG113: C57.2 IC33.1 IC34.4 R31.1
SIG115: C57.1 IC34.3 R30.2 R31.2
SIG122: C54.2 IC34.1 R25.2 R28.1
SIG129: C56.1 IC35.1 IC36.4 R29.2
SIG131: C56.2 IC36.3 R29.1 R32.2
SIG138: C55.1 IC36.1 R26.1 R27.2
SIG144: IC1.1(VBIAS) TP12.1
SIG271: C52.1 CN8.1 R20.1 R22.2 R24.2
SIG275: C53.1 D10.C/A(AC) IC2.3 R22.1
SIG374: C50.1 IC1.5(VREF) IC28.3 IC29.3 IC30.3 TP11.1 ; off-sheet Vref  [also labelled Vref]
SIG376: C46.1 IC32.3 R18.2 R19.2
Vref_in_u: C47.1 IC28.1 IC28.4 R18.1 R21.2 TP62.1 ; off-sheet Vref_in_u
Vref_in_v: C54.1 IC29.1 IC29.4 R28.2 R30.1 TP63.1 ; off-sheet Vref_in_v
Vref_in_w: C55.2 IC30.1 IC30.4 R27.1 R32.1 TP64.1 ; off-sheet Vref_in_w

Not connected (* = marked no-connect by the designer): CN8 NC1 NC2; IC31 5; IC32 5; IC33 5; IC34 5; IC35 5; IC36 5

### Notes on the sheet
- Fc = 200.5kHz
- EC2F103A2-40113
- THERMISTOR
- Labels drawn without touching a wire or pin: SIG276

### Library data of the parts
C46 C47 C54 C57 = C: OriginalSymbolOrigin: (2540,7620); COMP: -C-GCM1555C1H270FA16D
C48 C50 C51 C140-C144 C146 C147 C149 C150 = C: as C1 on sheet 1
C52 = C: as C25 on sheet 2
C53 = C: as C104 on sheet 5
C55 C56 = C#1: OriginalSymbolOrigin: (2540,7620); CaptureCellPackProp: C##1; COMP: -C-GCM1555C1H270FA16D
CN8 = BM02B_PASS_1_TFT_LF__SN_: Connector, 250V, 3A; MANUFACTURER: JST; COMP: -CN-BM02B-PASS-1-TFT_LF_SN; NOTE: 2pin; TIME: 11:39:42; UPDATEUSER: t5459927; UPDATETIME: 16:51:32; SAVECOUNT: 4; SAVEAREA0: -29189,-27933,36825,20394; OriginalSymbolOrigin: (0,0)
D10 = DEW: SAVEAREA0: -10024,-234,32508,20938; TIME: 14:49:55; UPDATEUSER: 19990028; UPDATETIME: 14:00:58; SAVECOUNT: 4; OriginalSymbolOrigin: (5080,17780); COMP: -D-1SS423_TE85L_F_AC
IC1 = REF2025AIDDCT: Voltage References; MANUFACTURER: Texas Instruments; COMP: -IC-REF2025AIDDCT; TIME: 11:39:41; UPDATEUSER: t5459927; UPDATETIME: 14:37:37; SAVECOUNT: 2; SAVEAREA0: -19574,-17685,36869,8033; OriginalSymbolOrigin: (0,0)
IC2 IC28-IC30 = TC75S103F: as IC10 on sheet 4
IC31-IC36 = OPA607IDCKR: COMP: IC-OPA607IDCKR; TIME: 16:31:59; UPDATEUSER: t5459927; UPDATETIME: 14:13:01; SAVECOUNT: 17; SAVEAREA0: -9767,-7670,25158,17897; OriginalSymbolOrigin: (2540,10160)
R18 R23 R25 R26 R30 R32 = R: OriginalSymbolOrigin: (5080,5080); VAL2: 100mW; COMP: -R-ERA3AEB223V
R19 R21 R28 R31 = R: OriginalSymbolOrigin: (5080,5080); VAL2: 100mW; COMP: -R-ERA3AEB2942V
R20 = R: OriginalSymbolOrigin: (5080,5080); COMP: -R-ERJ3EKF2201V; VAL2: 100mW
R22 = R: OriginalSymbolOrigin: (5080,5080); COMP: -R-RK73H1JTTD1001F; VAL2: 125mW
R24 = R: OriginalSymbolOrigin: (5080,5080); COMP: -R-RK73H1JTTD1003F; VAL2: 100mW
R27 R29 = R#1: OriginalSymbolOrigin: (5080,5080); CaptureCellPackProp: R##1; VAL2: 100mW; COMP: -R-ERA3AEB2942V
TP10-TP15 TP62-TP64 = TP: as TP1 on sheet 1
U?#6 = WAKU_DEF100: PLOTTIME: HH:MM; SAVEAREA0: 22200,72372,612276,319236; TIME: 14:30:25; UPDATEUSER: t5459927; UPDATETIME: 09:21:33; SAVECOUNT: 7; OriginalSymbolOrigin: (10160,284480)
